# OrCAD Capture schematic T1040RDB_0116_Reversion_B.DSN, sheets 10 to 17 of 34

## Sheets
10 10 QE: size B
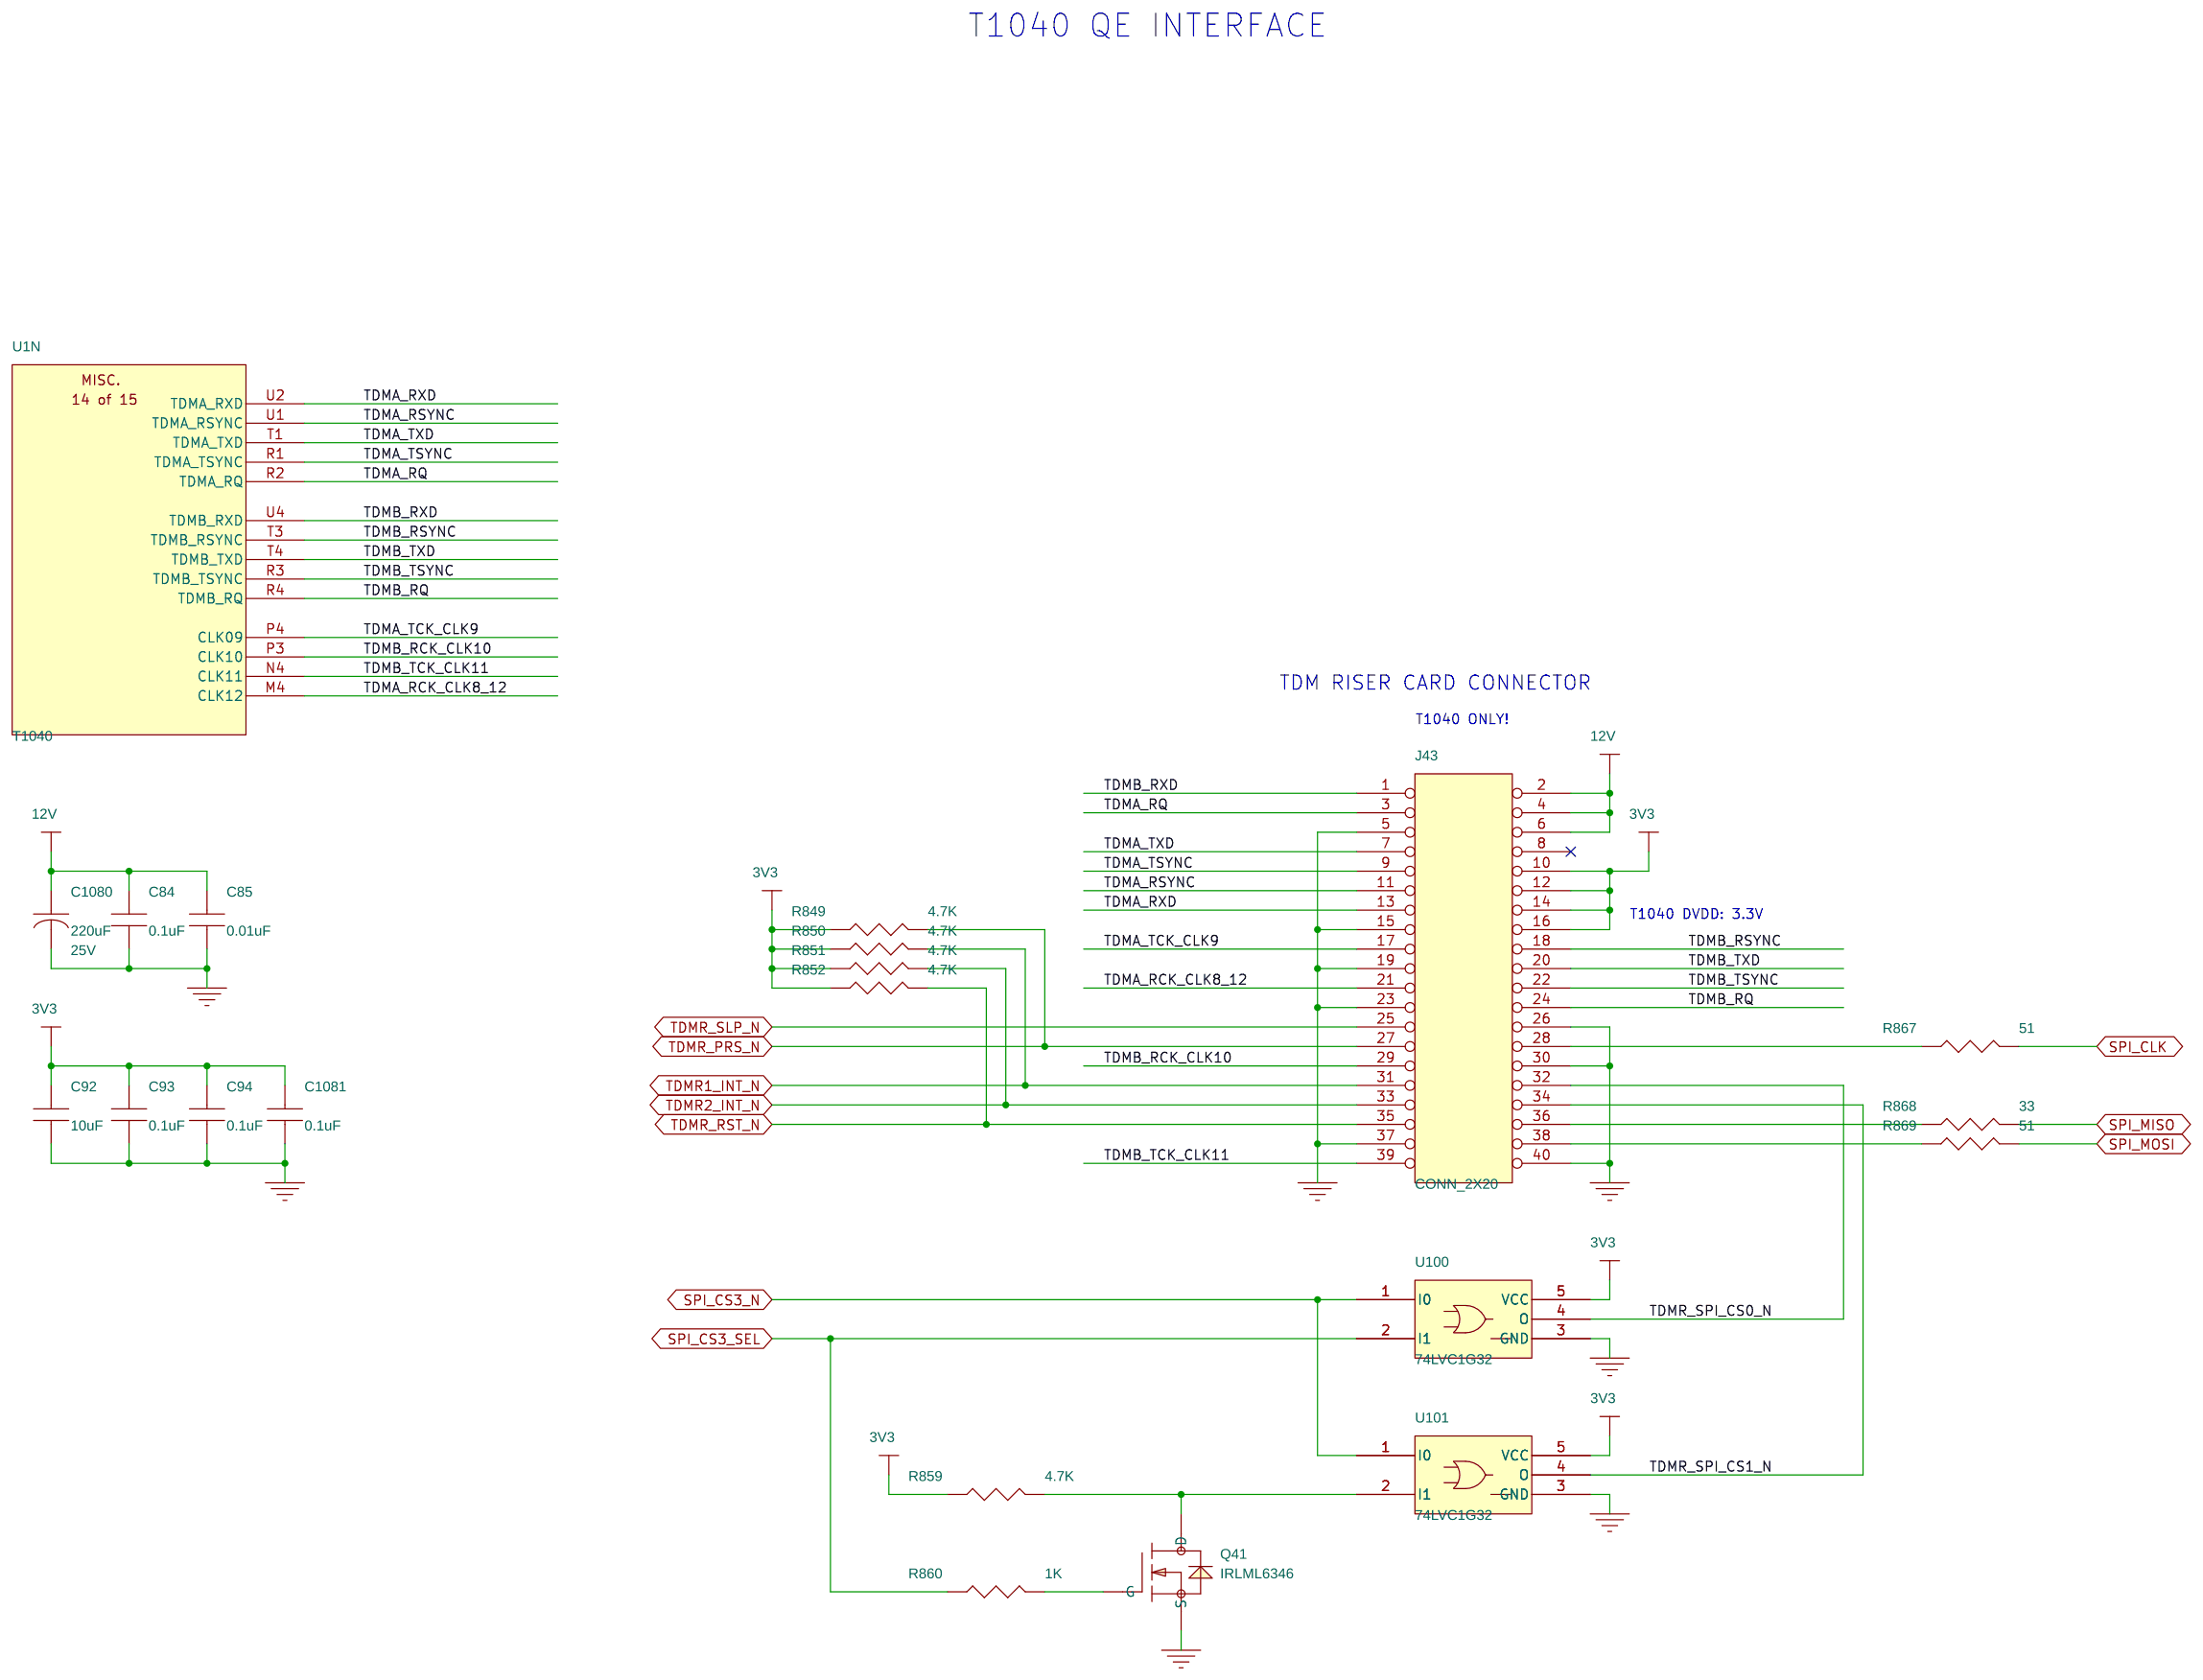
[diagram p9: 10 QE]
11 11 USB: size B
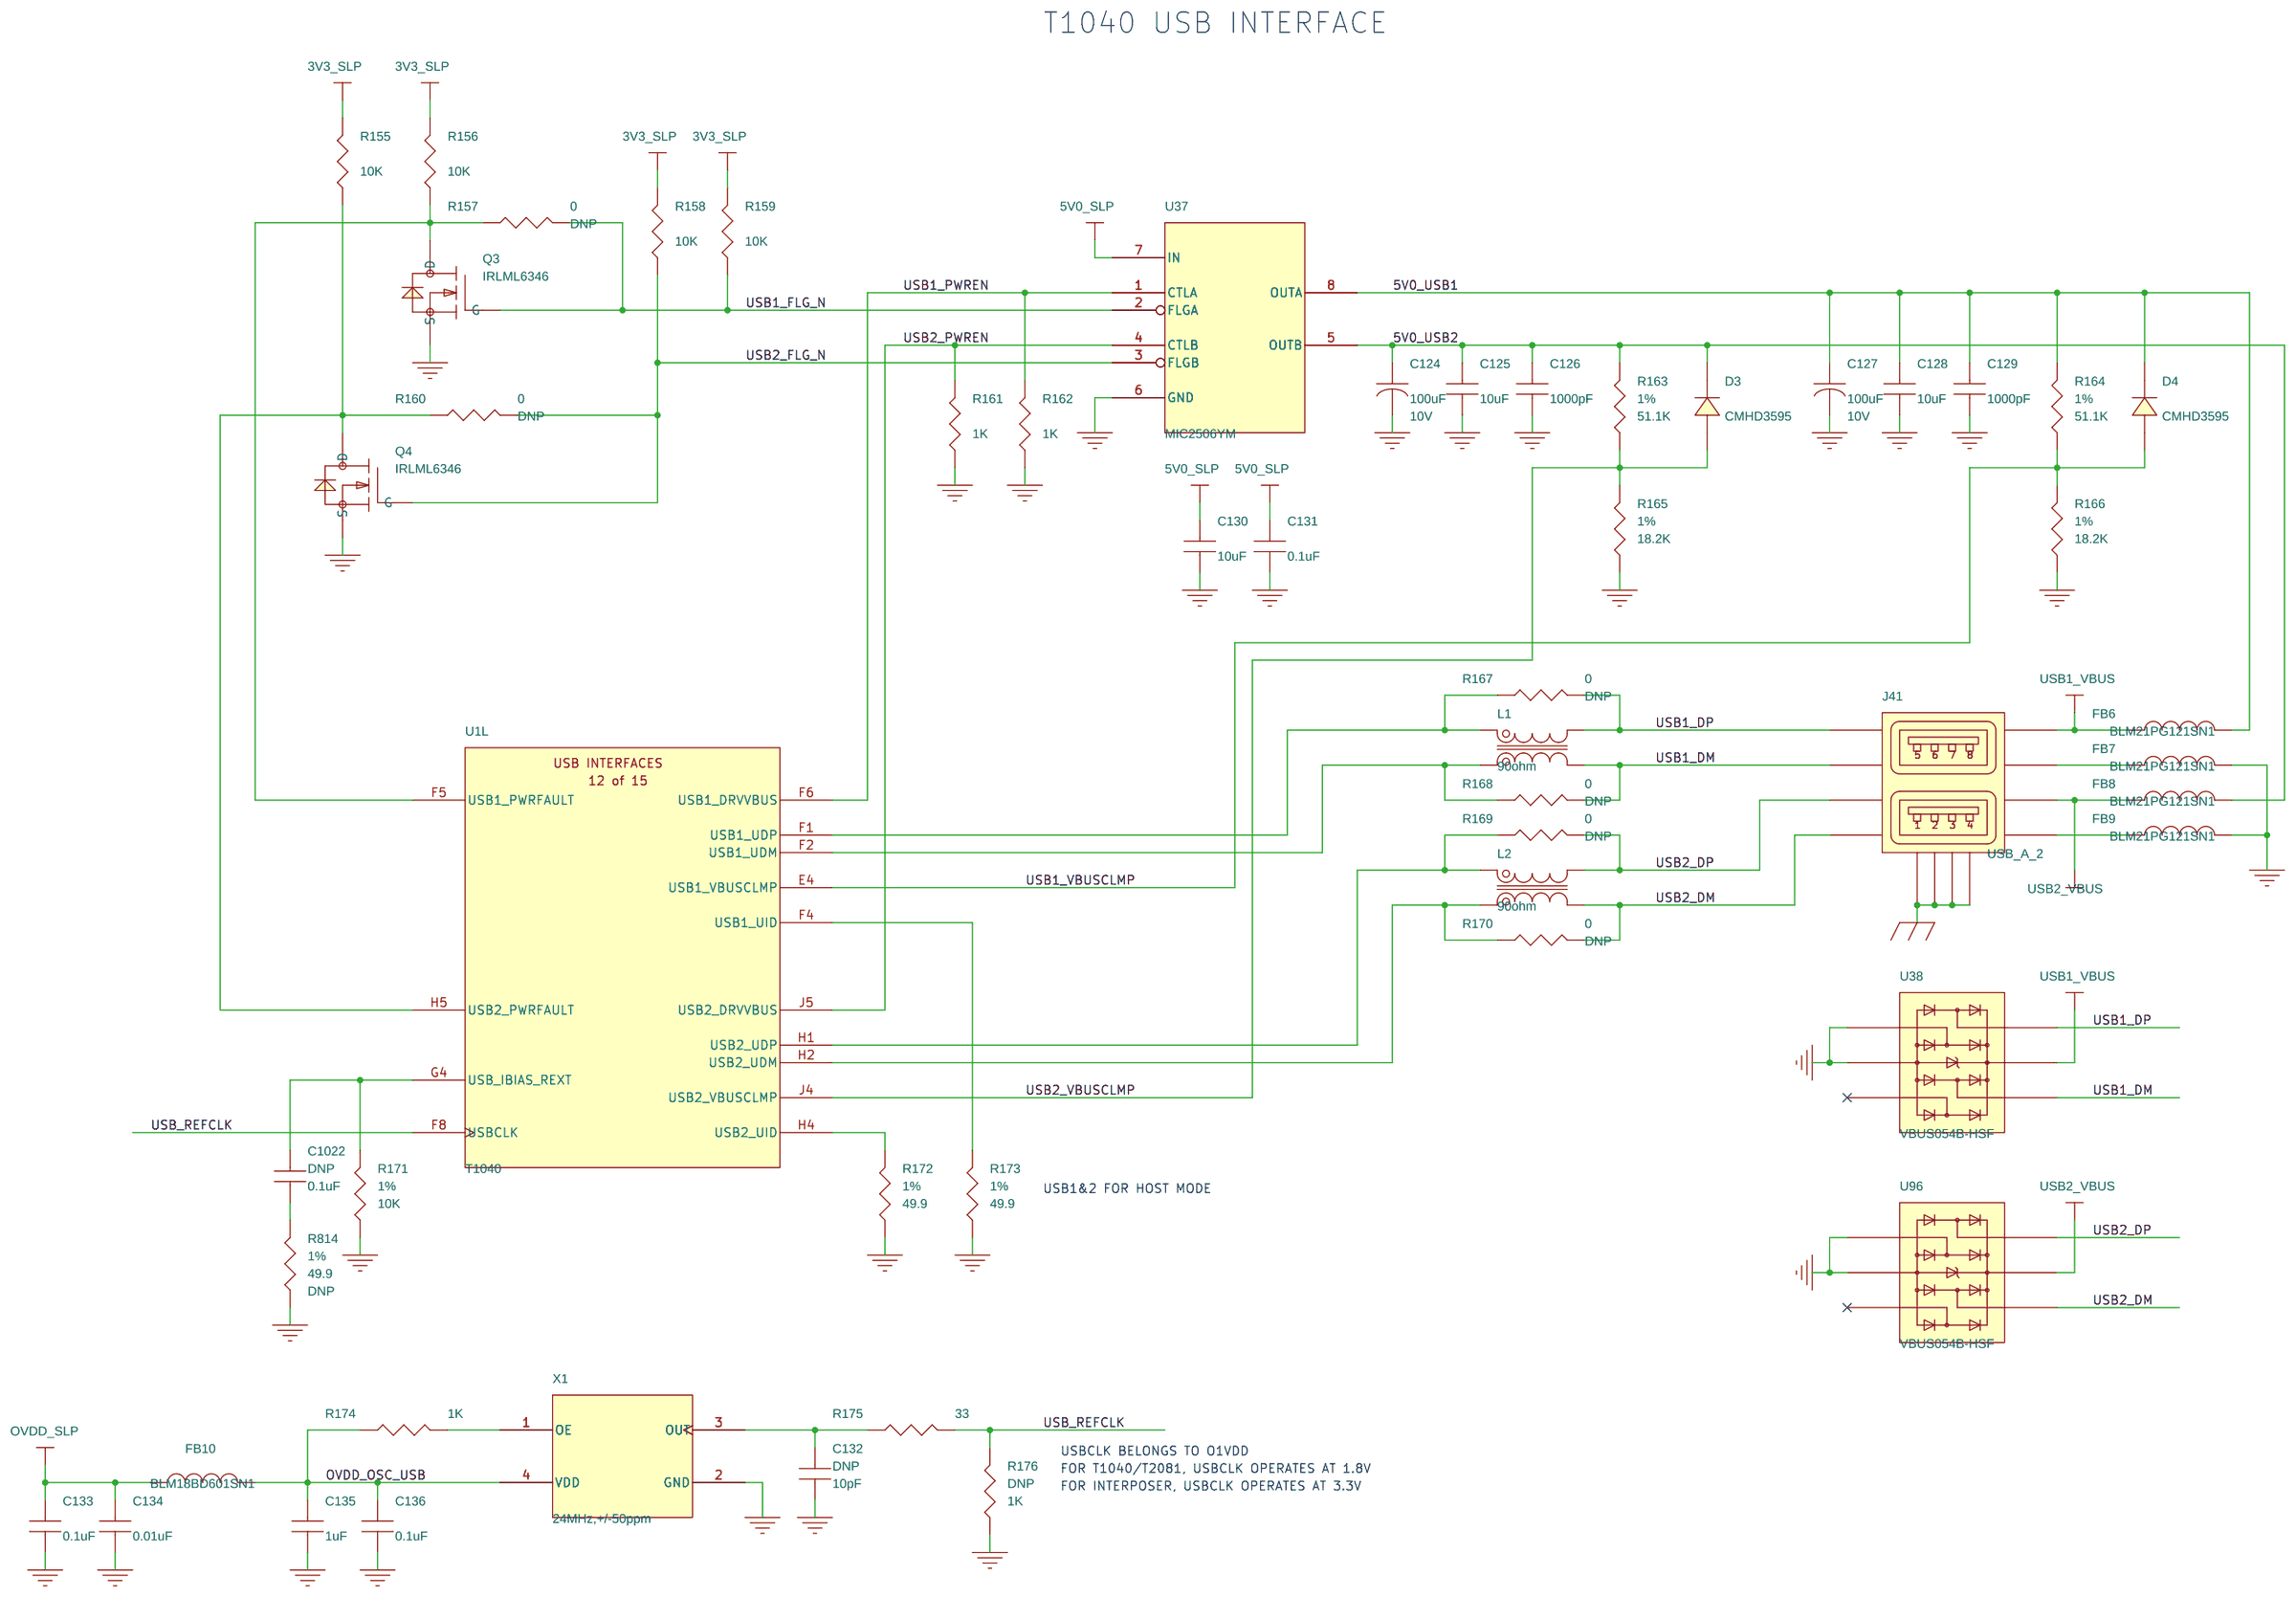
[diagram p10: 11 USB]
12 12 Proc Pwr: size B
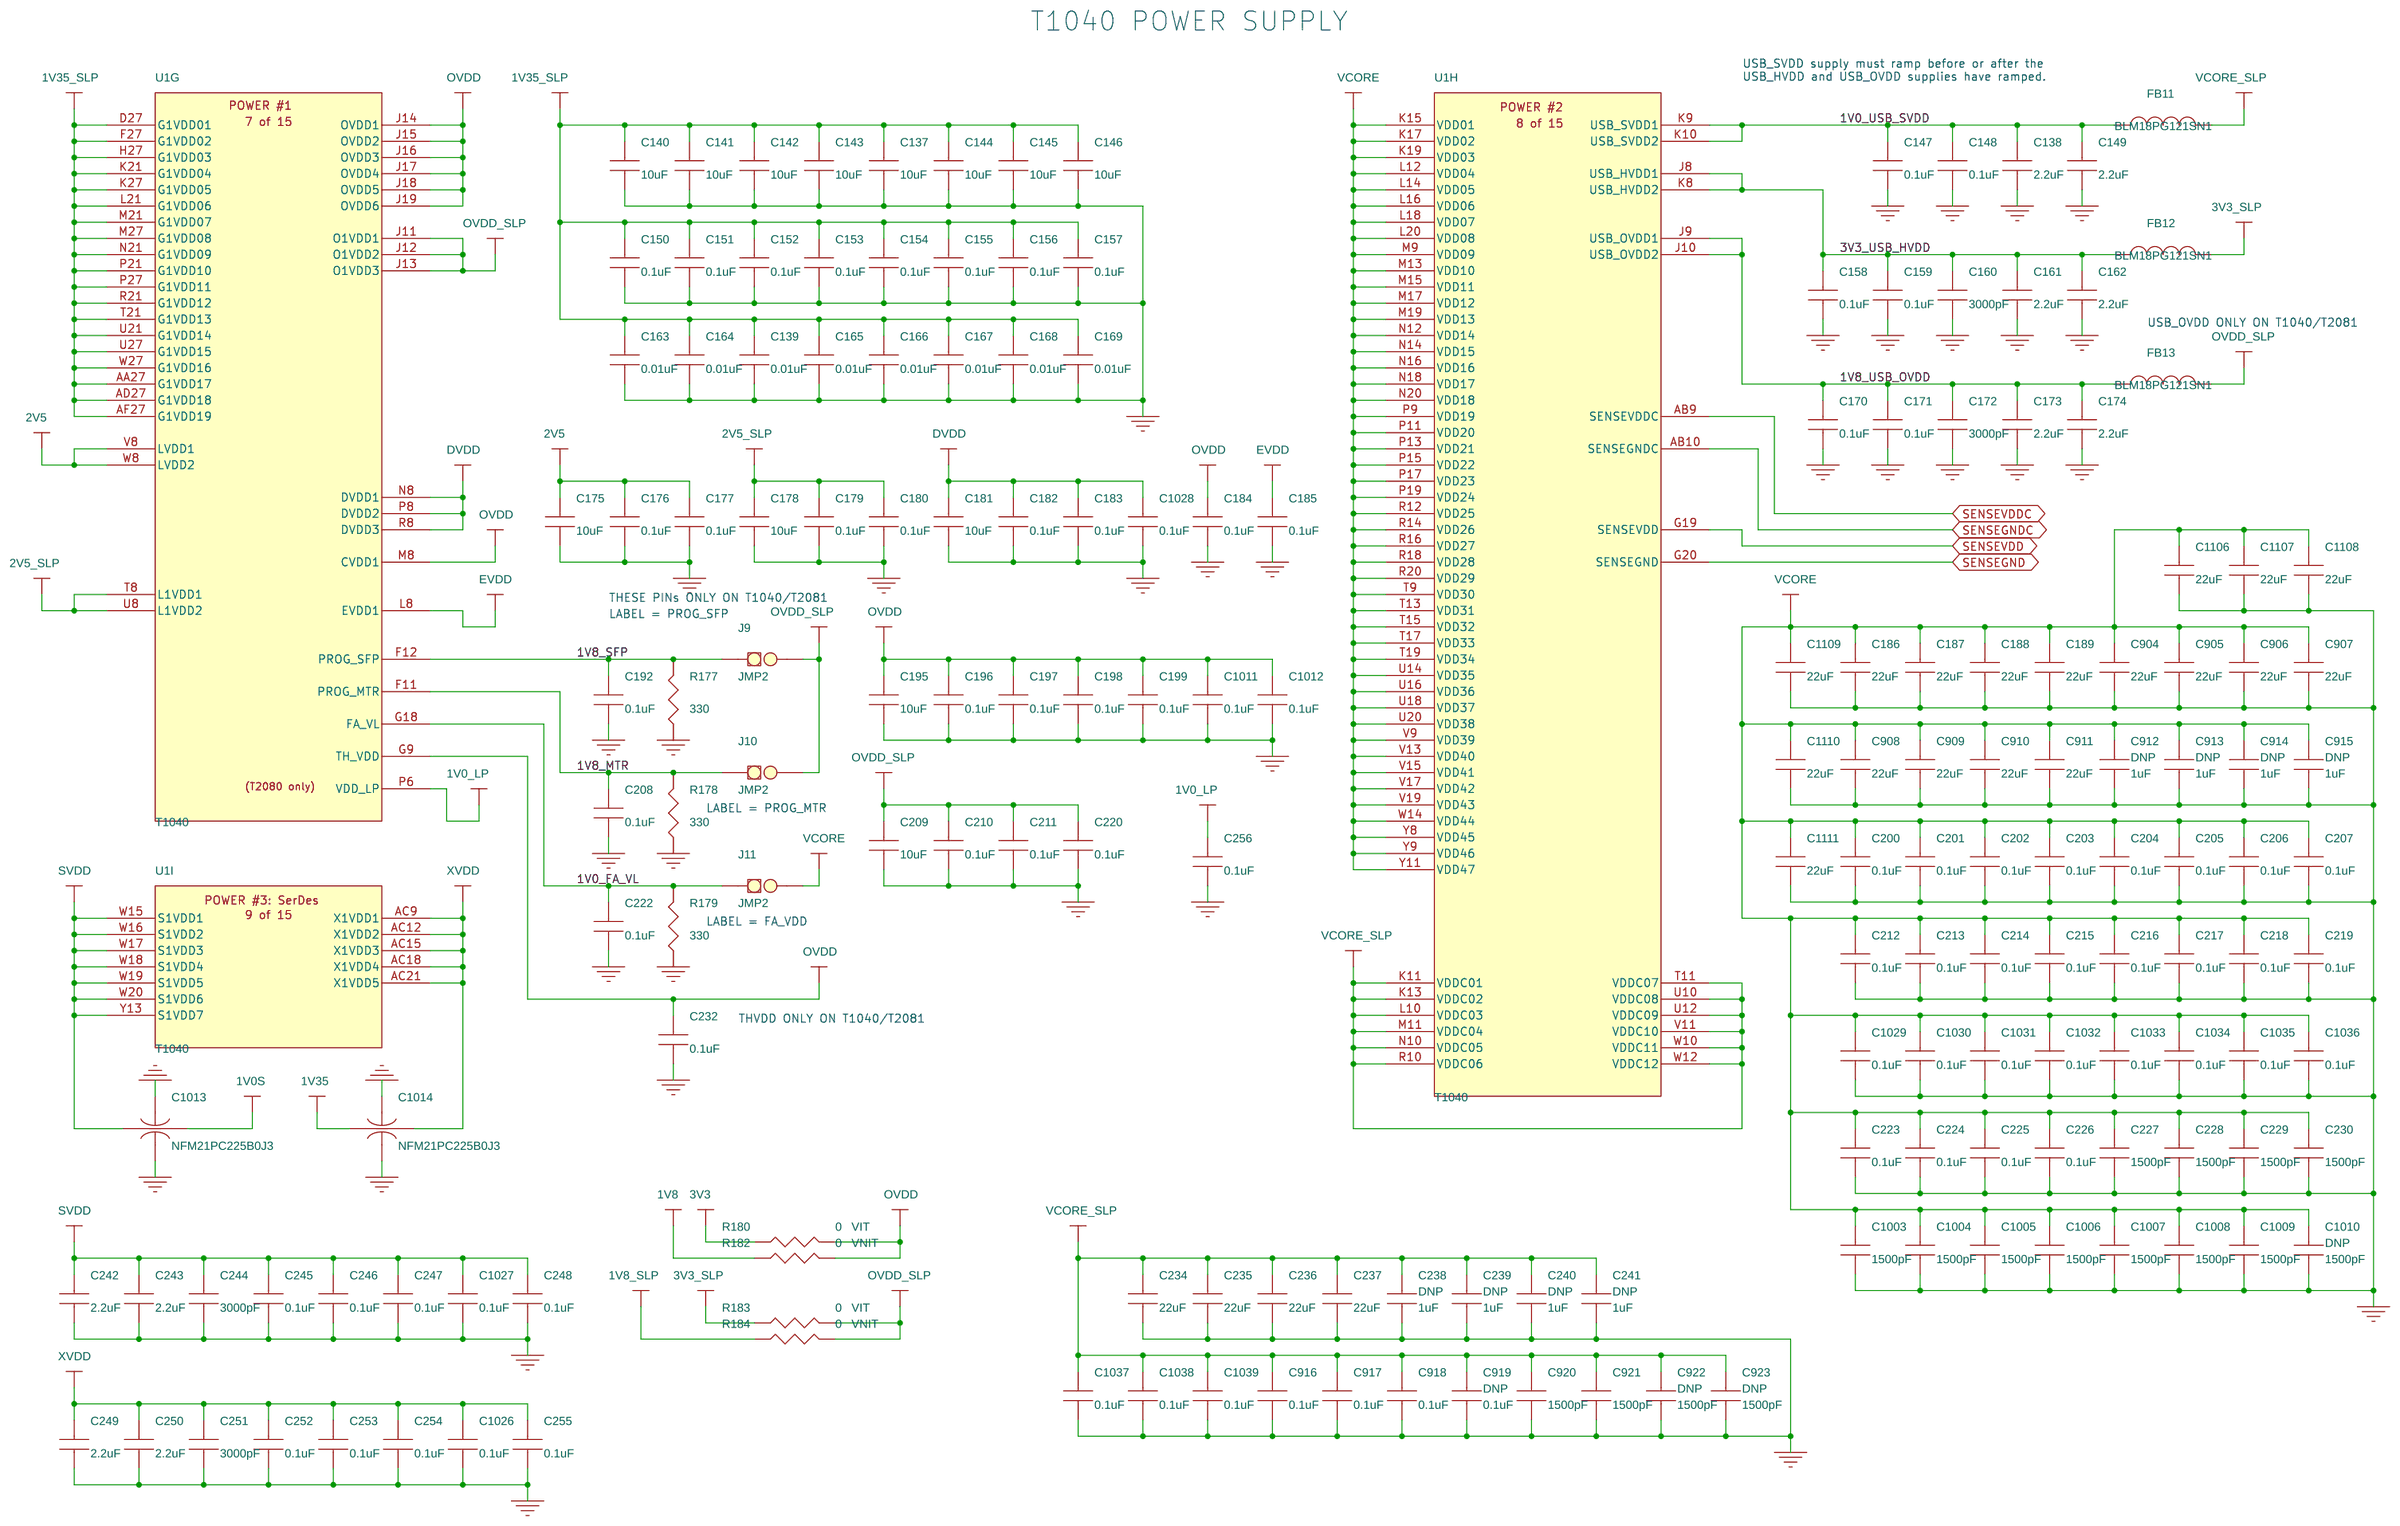
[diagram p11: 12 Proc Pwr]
13 13 Proc Gnd: size B
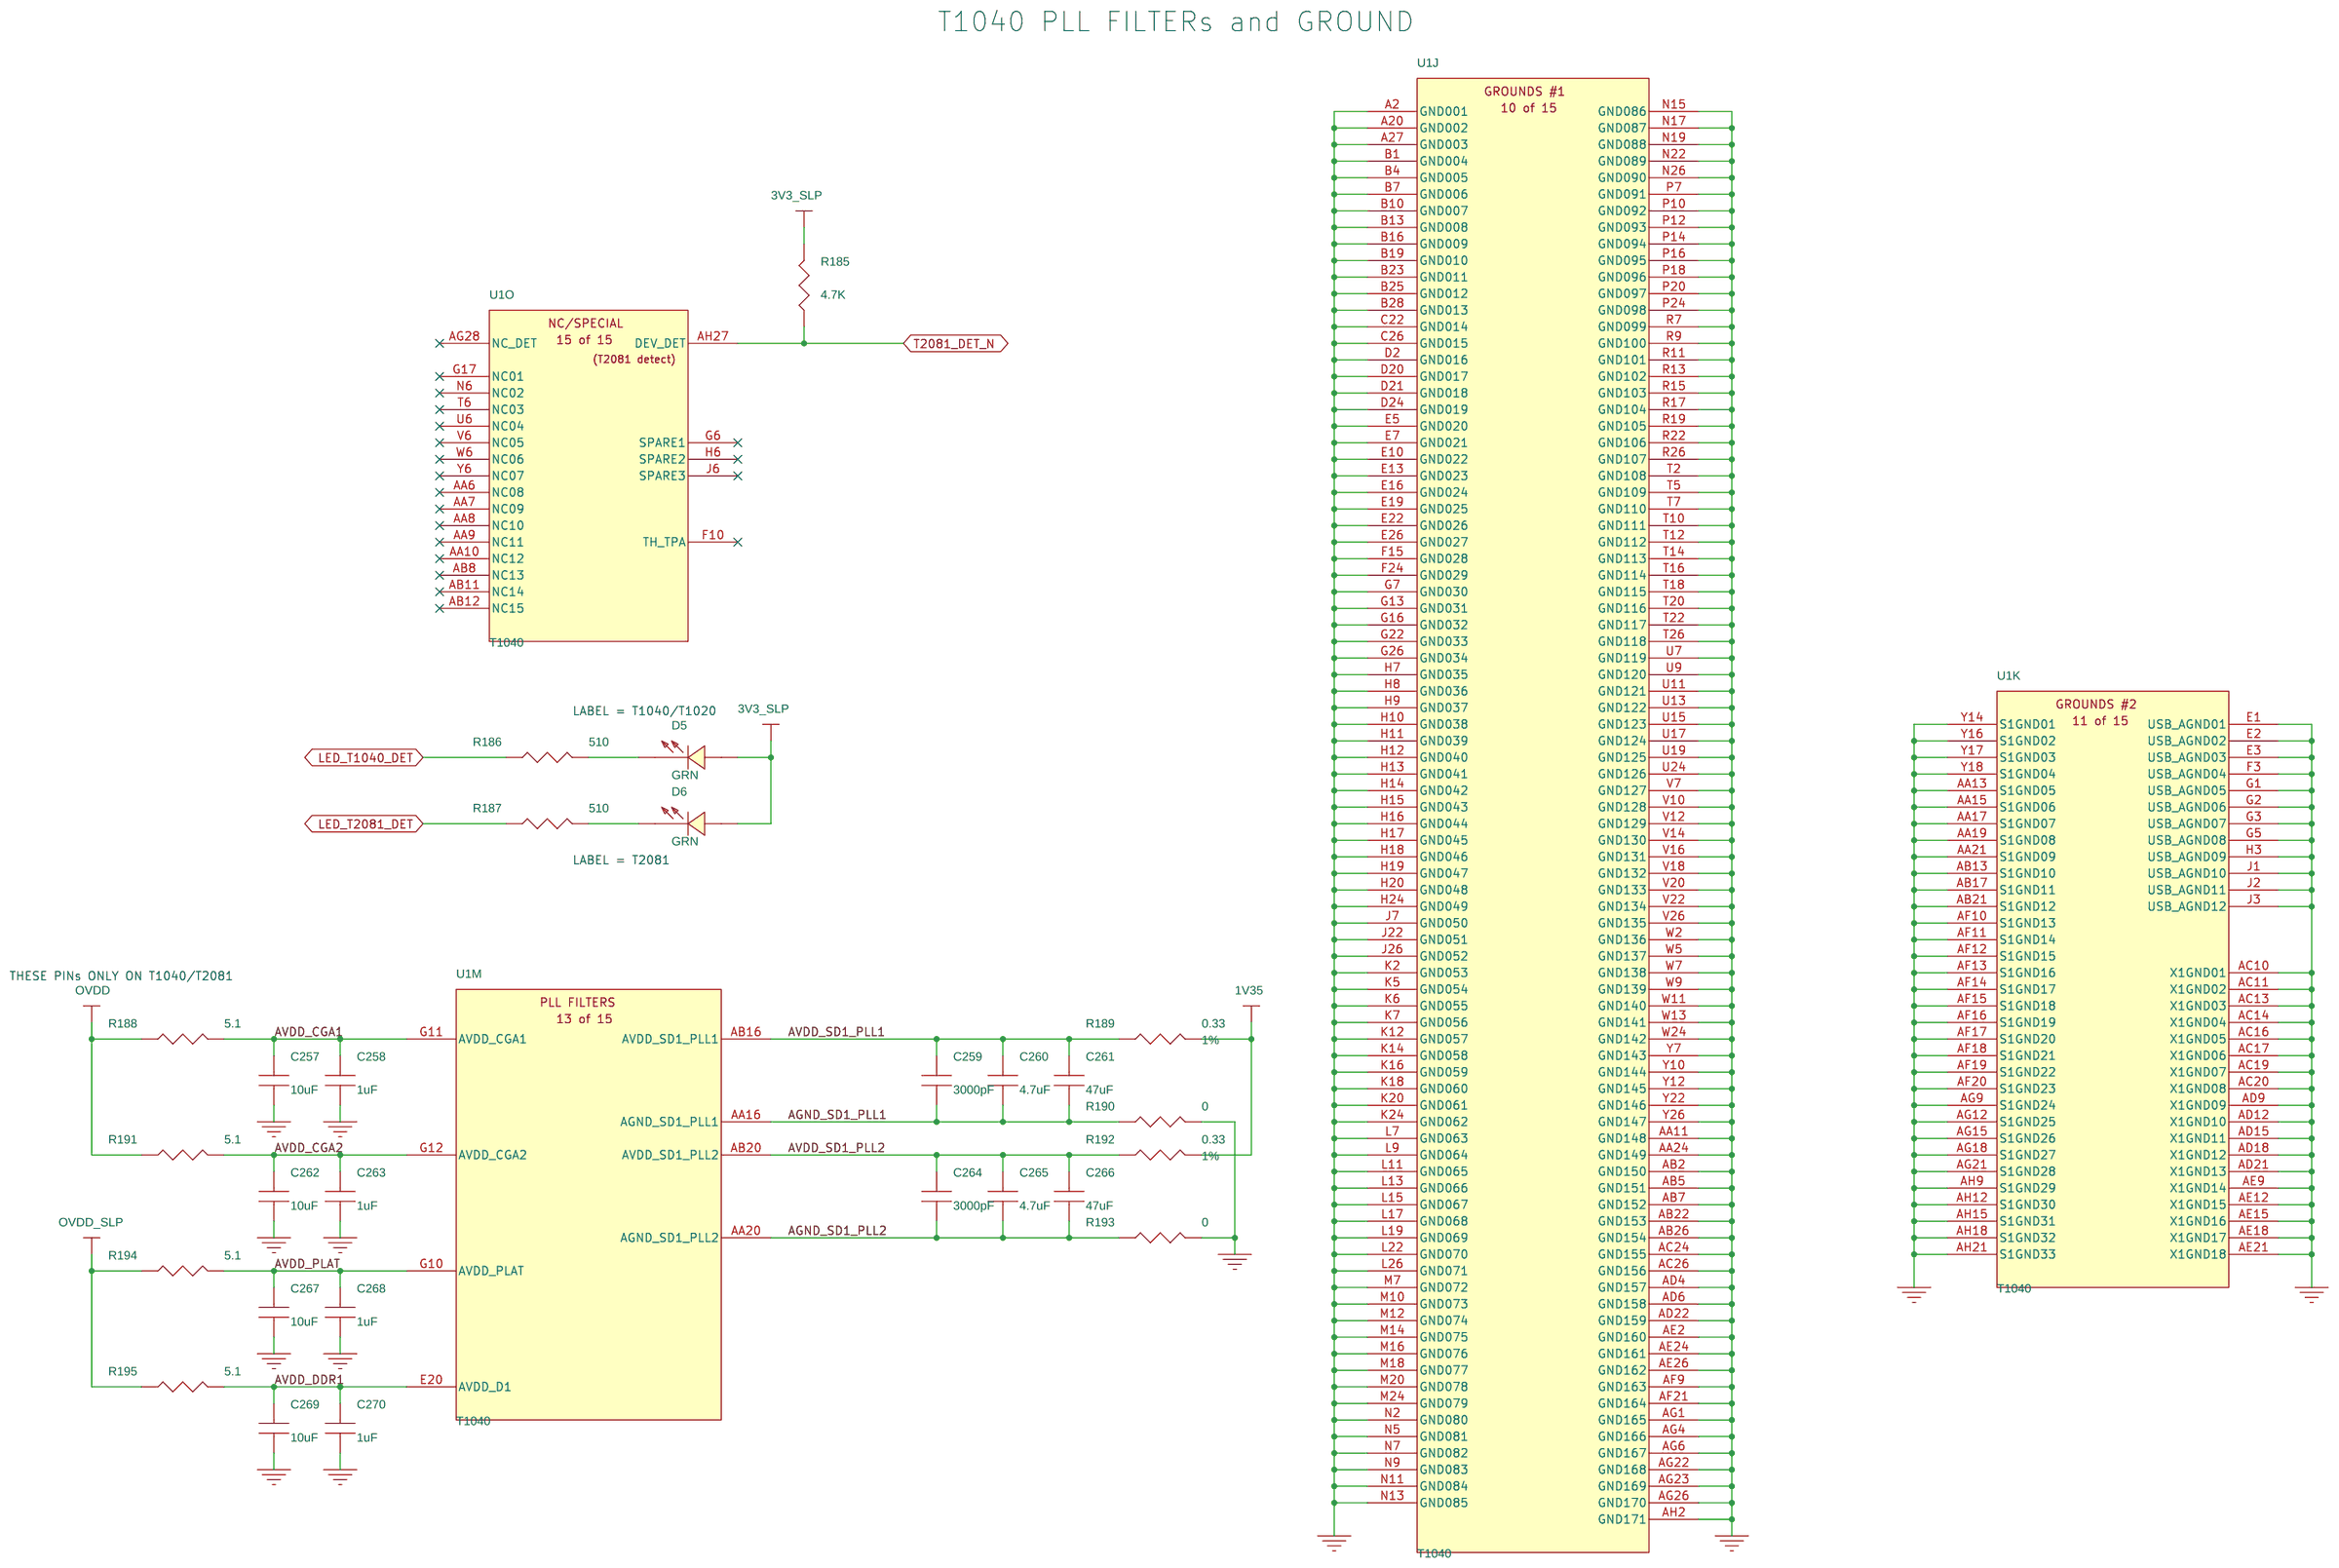
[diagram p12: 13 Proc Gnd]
14 14 UART&I2C: size B
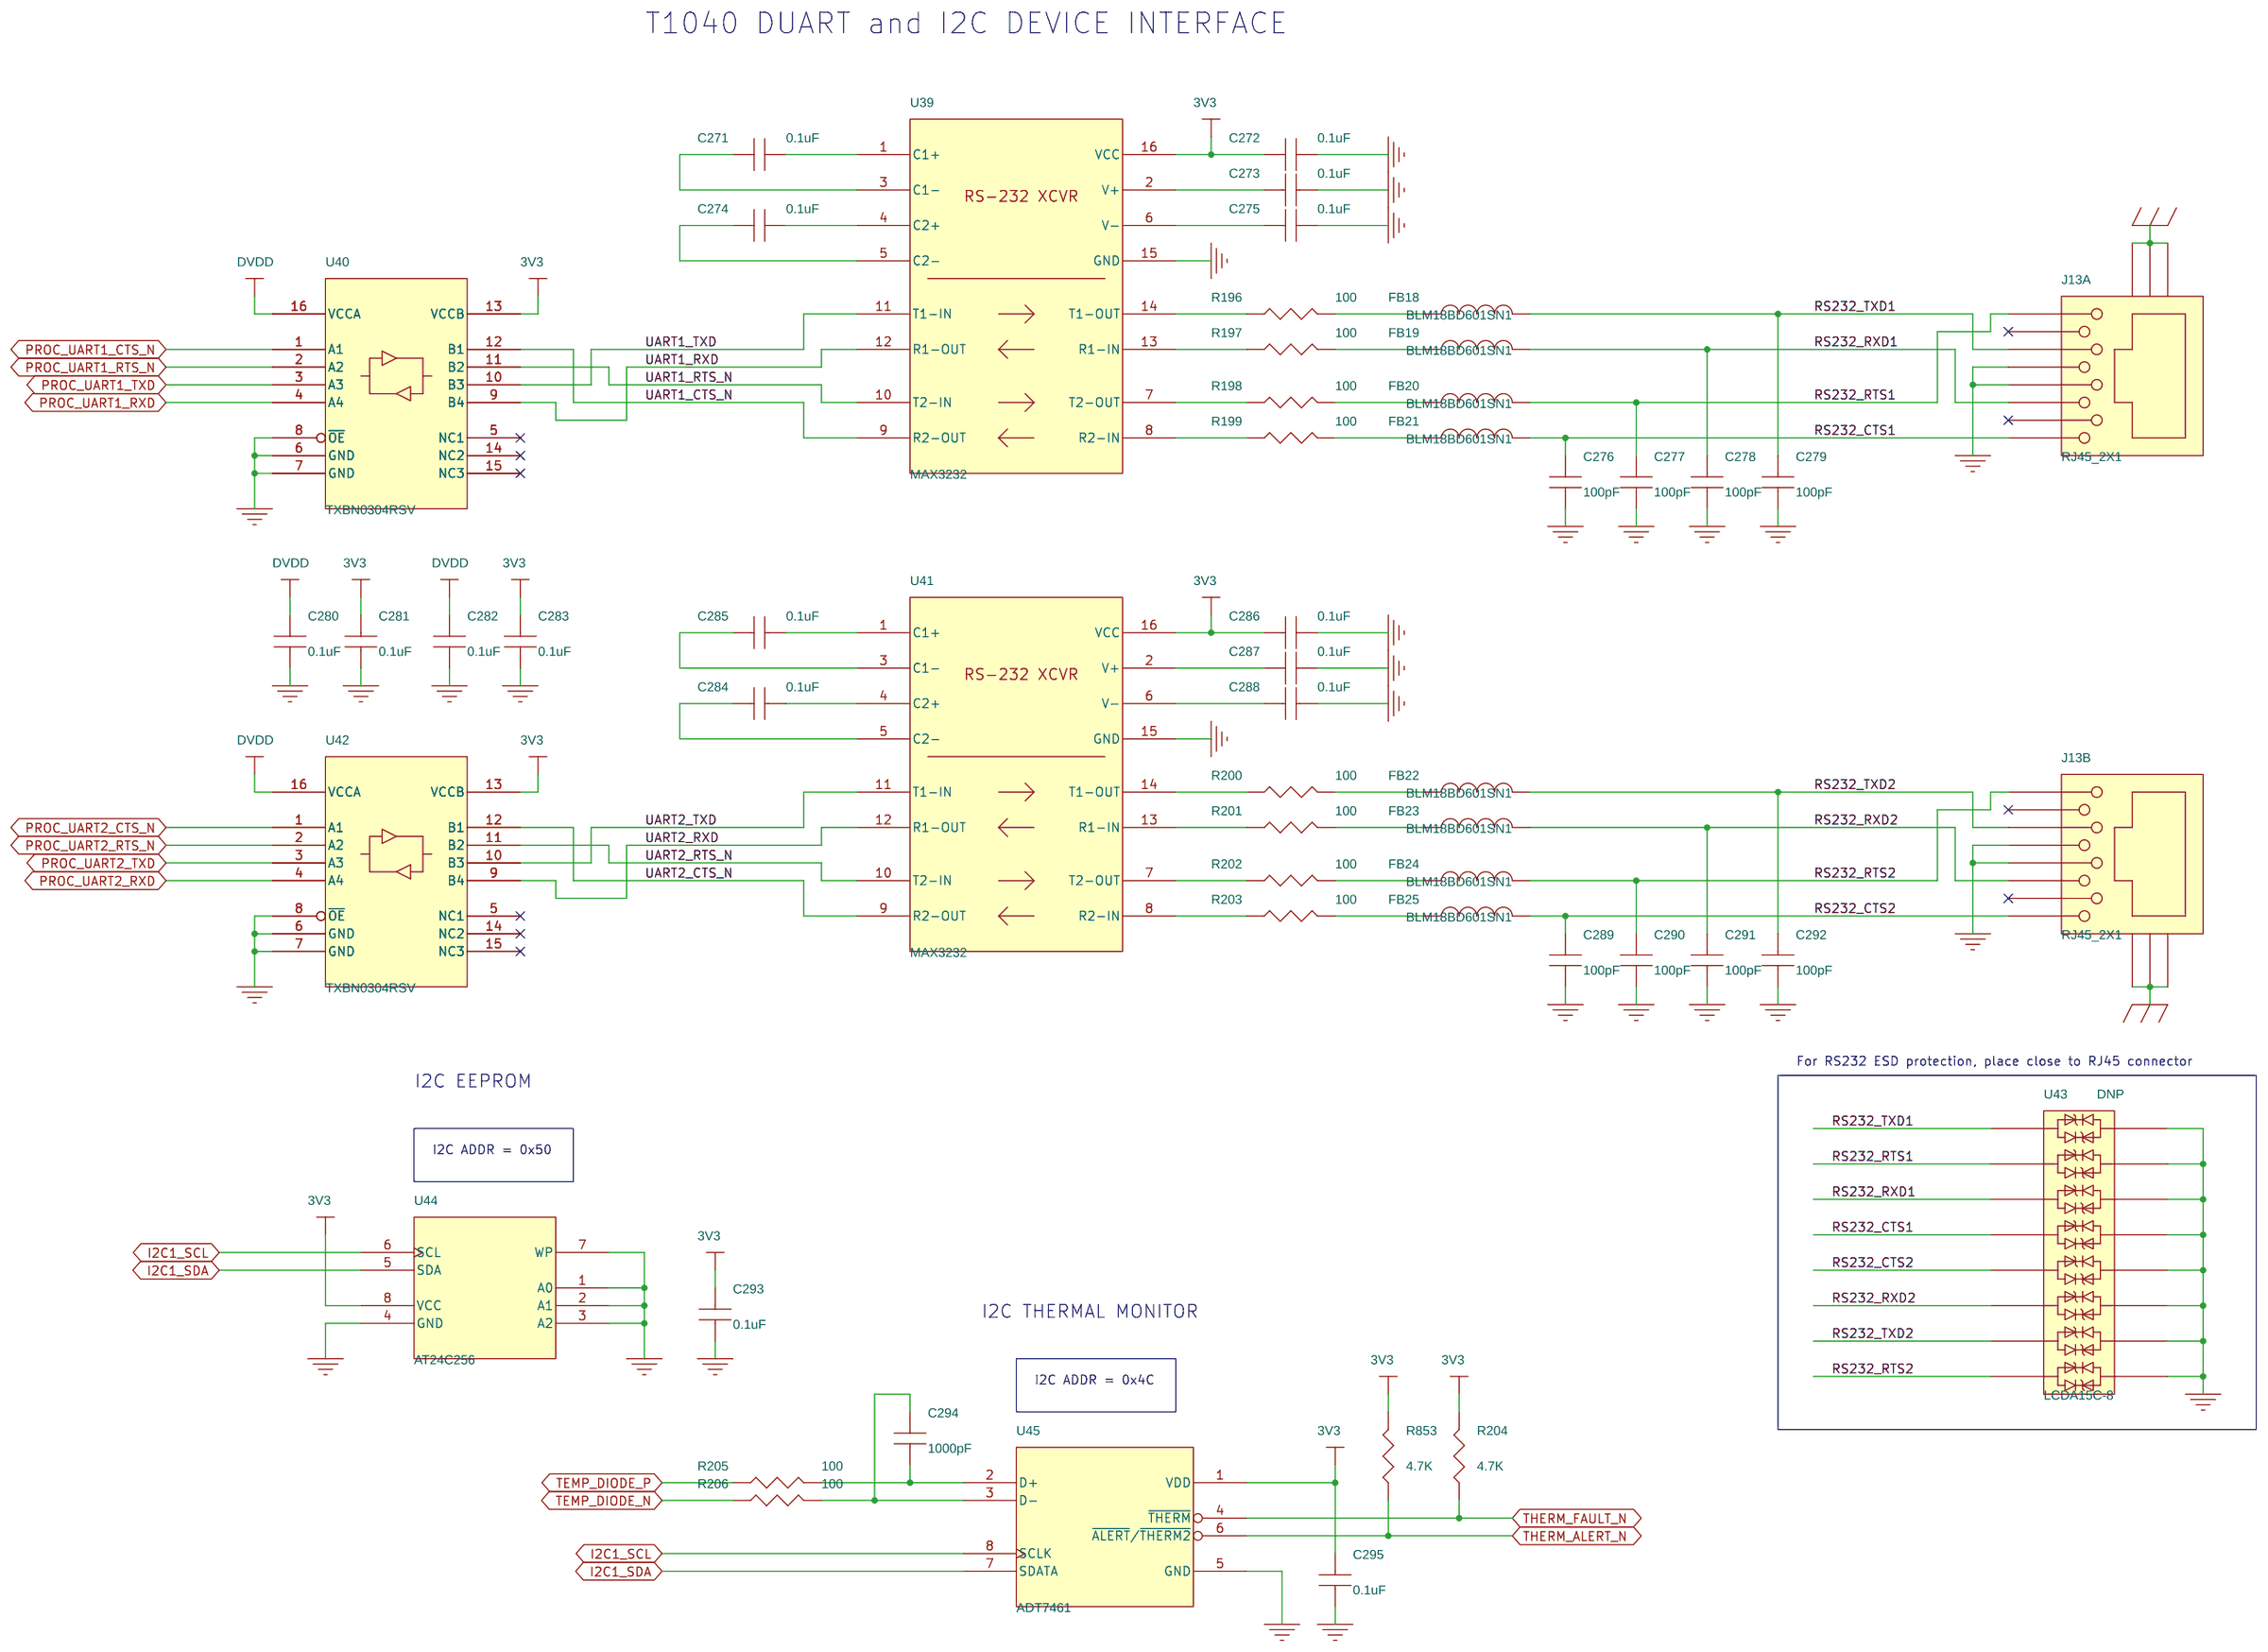
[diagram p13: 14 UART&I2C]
15 15 EC1 PHY: size B
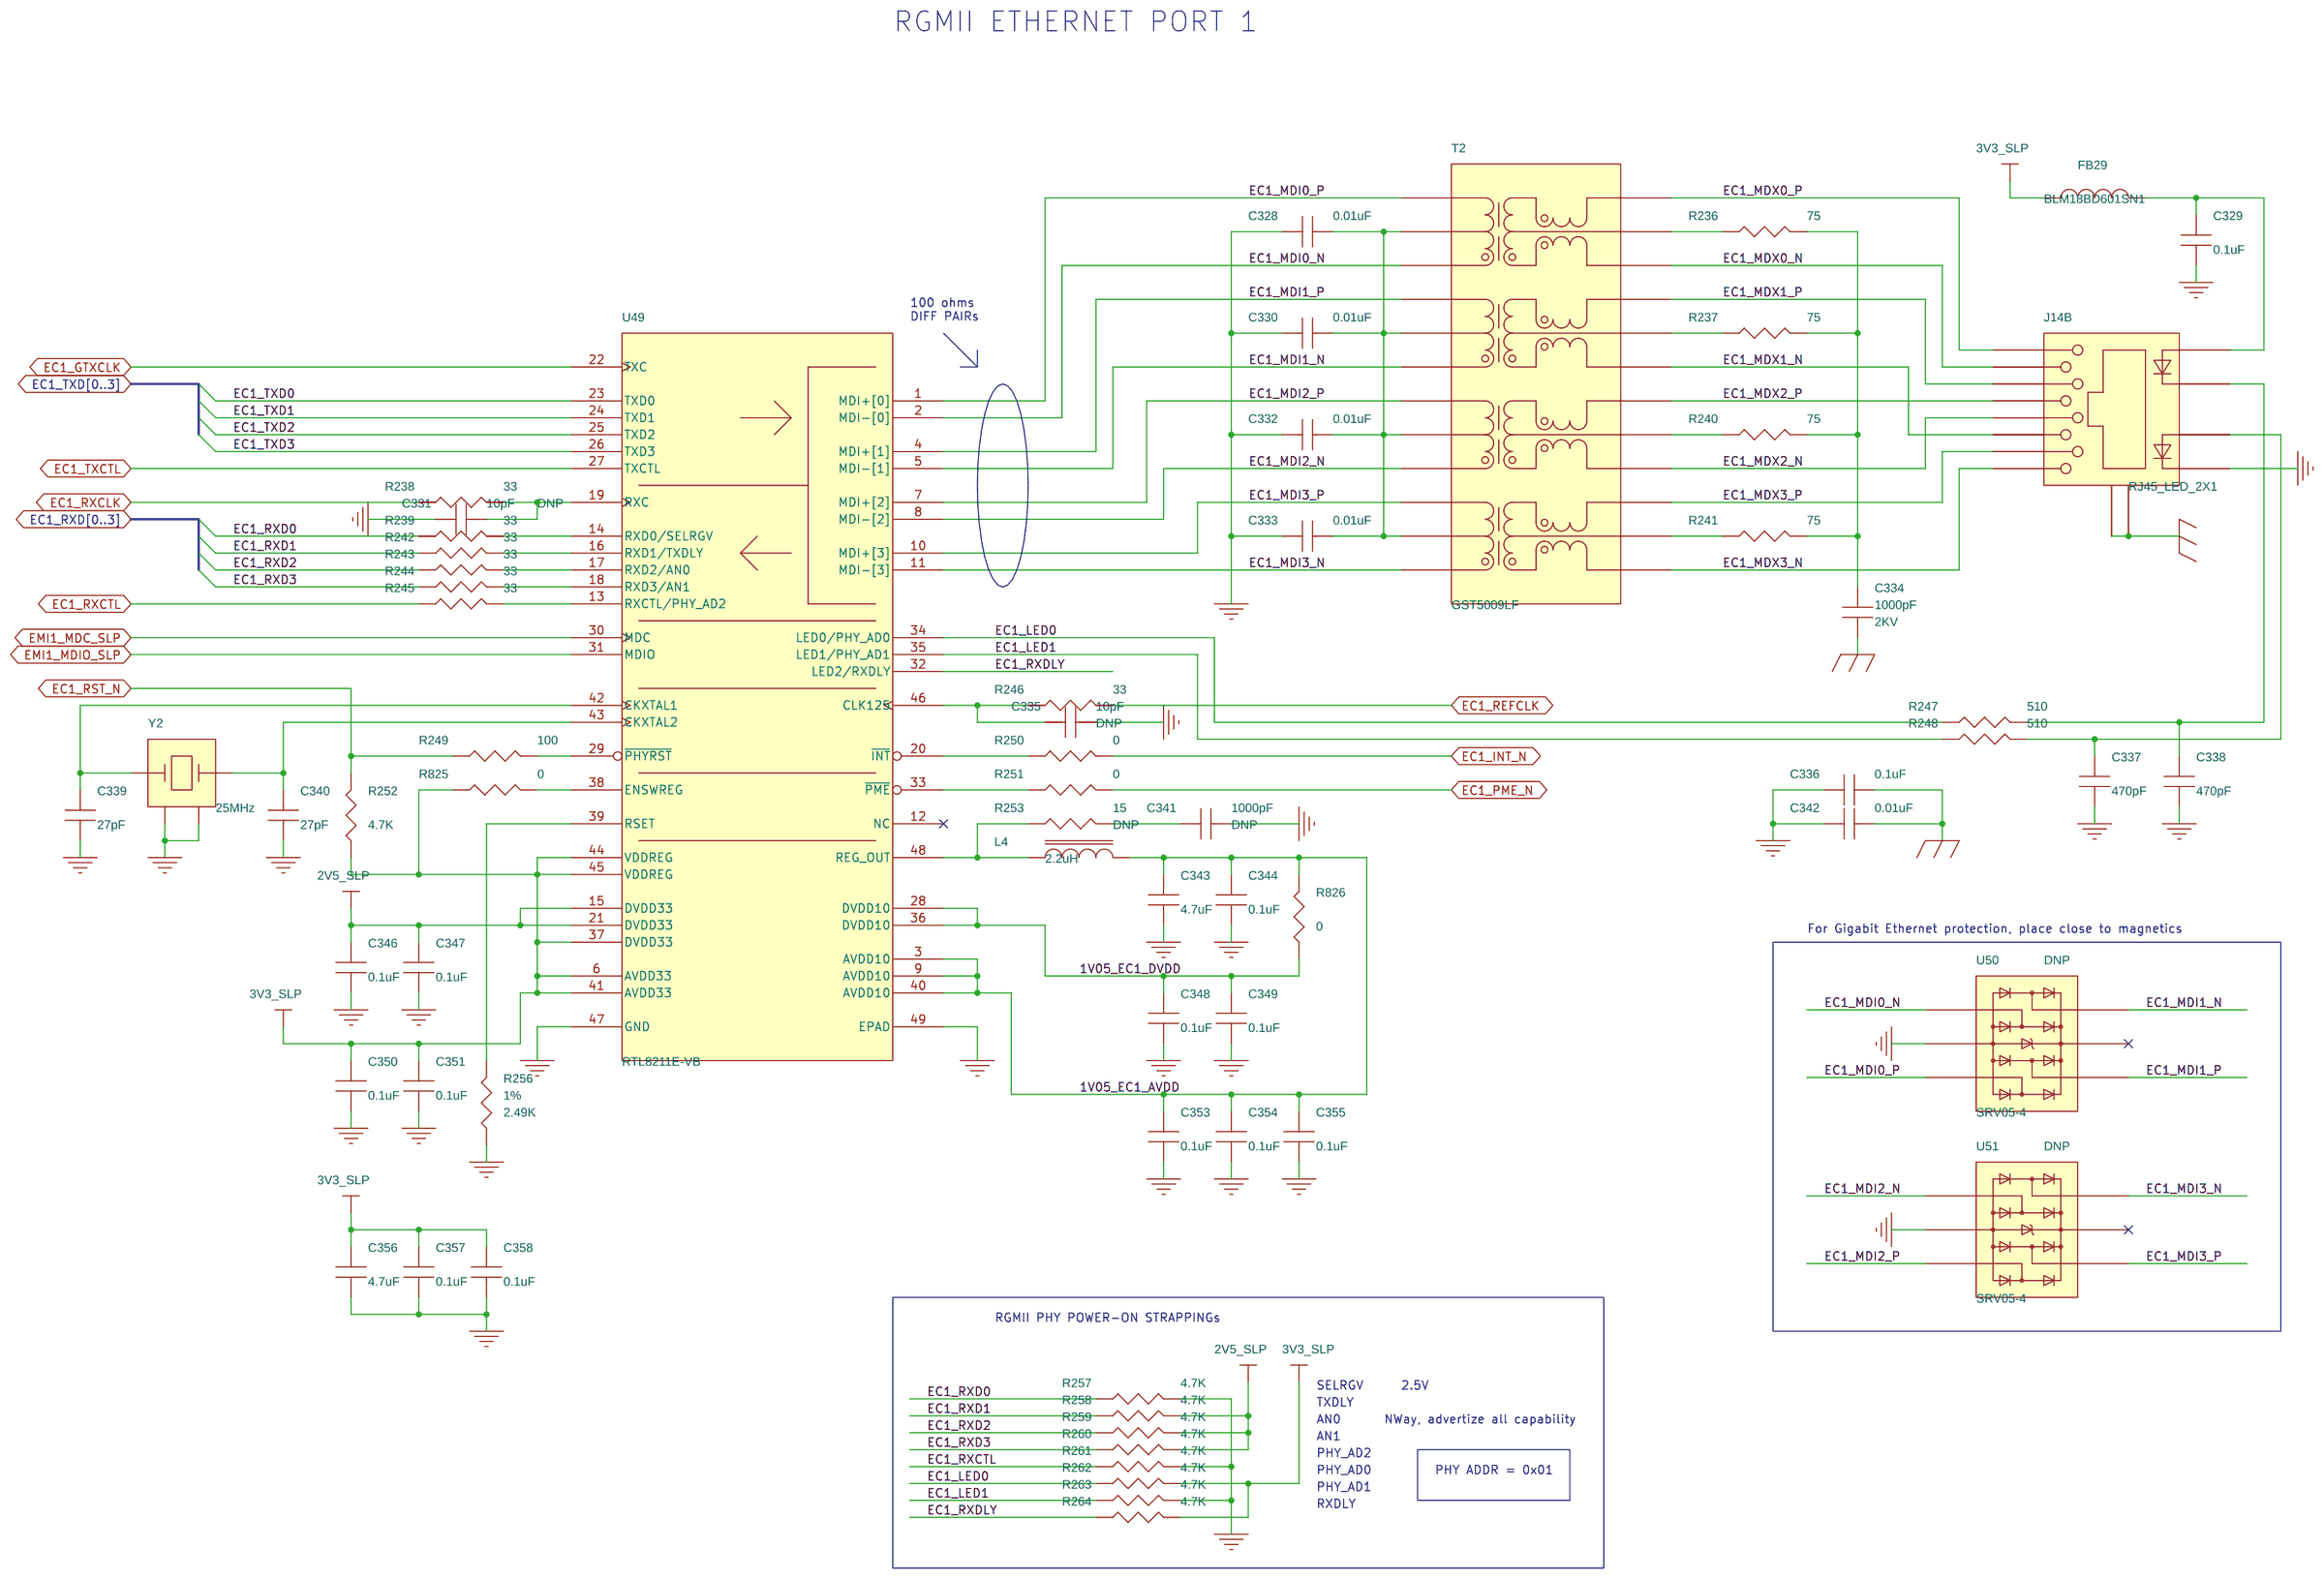
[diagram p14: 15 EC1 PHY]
16 16 EC2 PHY: size B
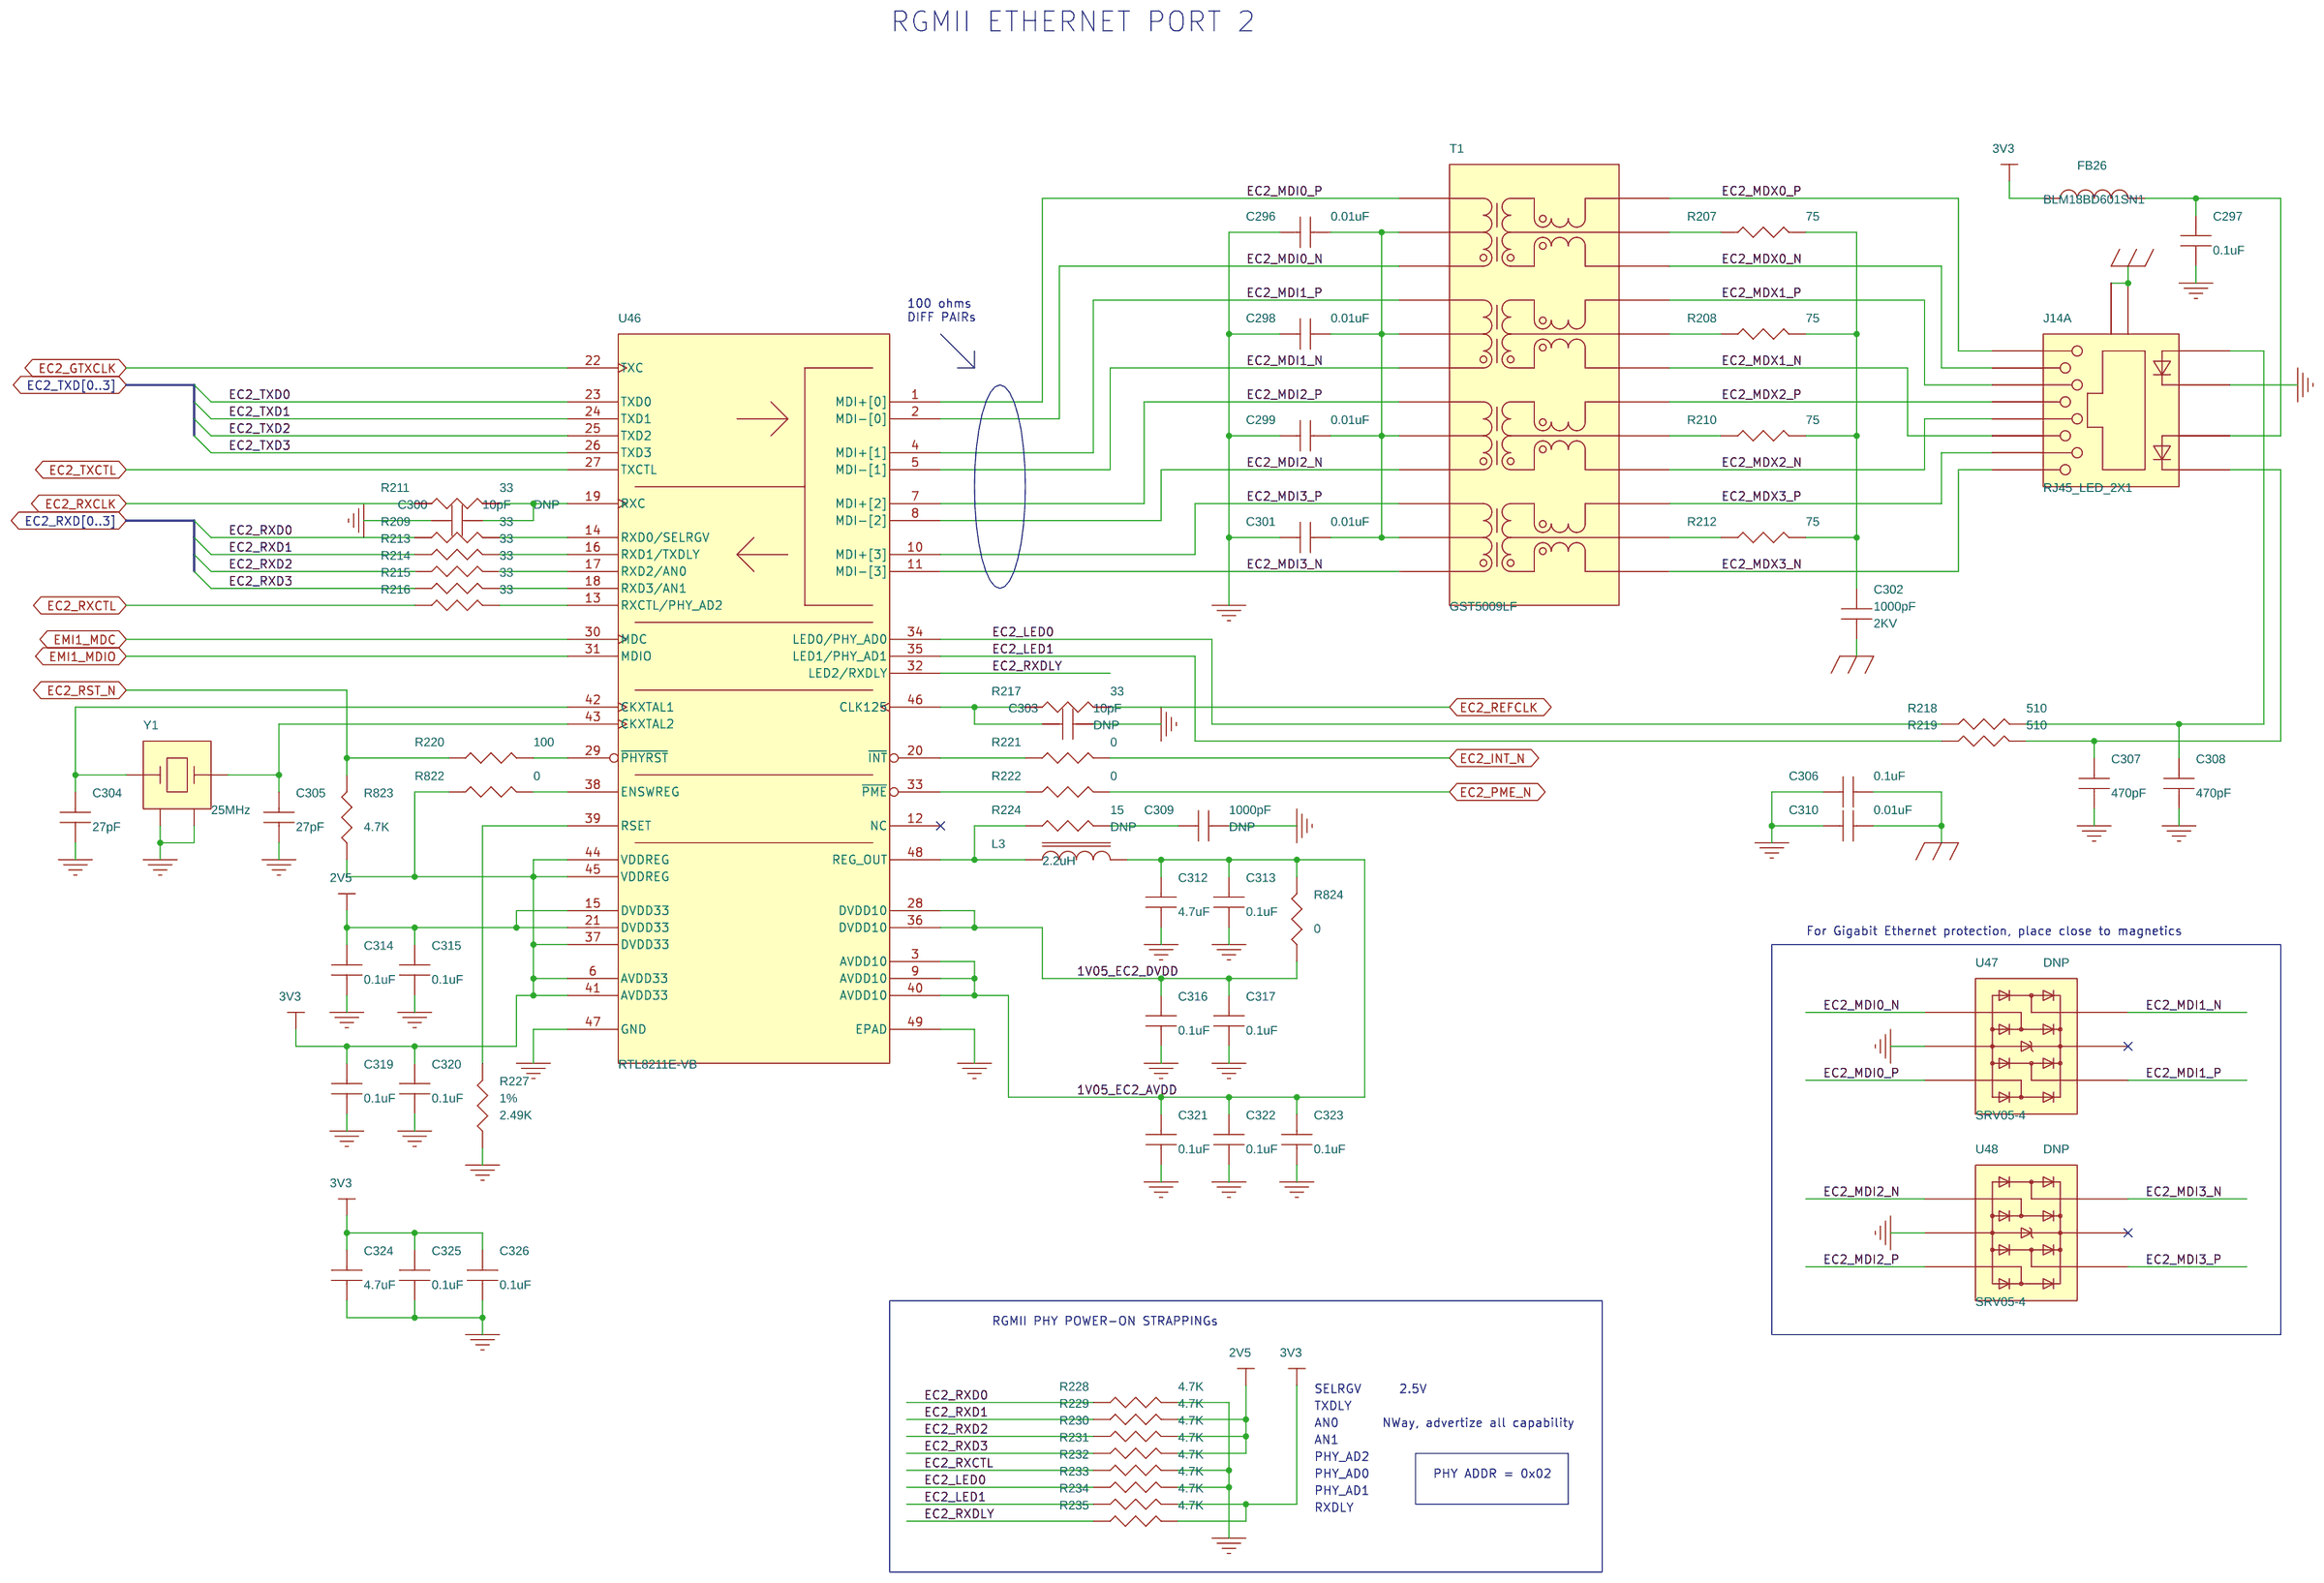
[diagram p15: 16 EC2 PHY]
17 17 SG PHY: size B
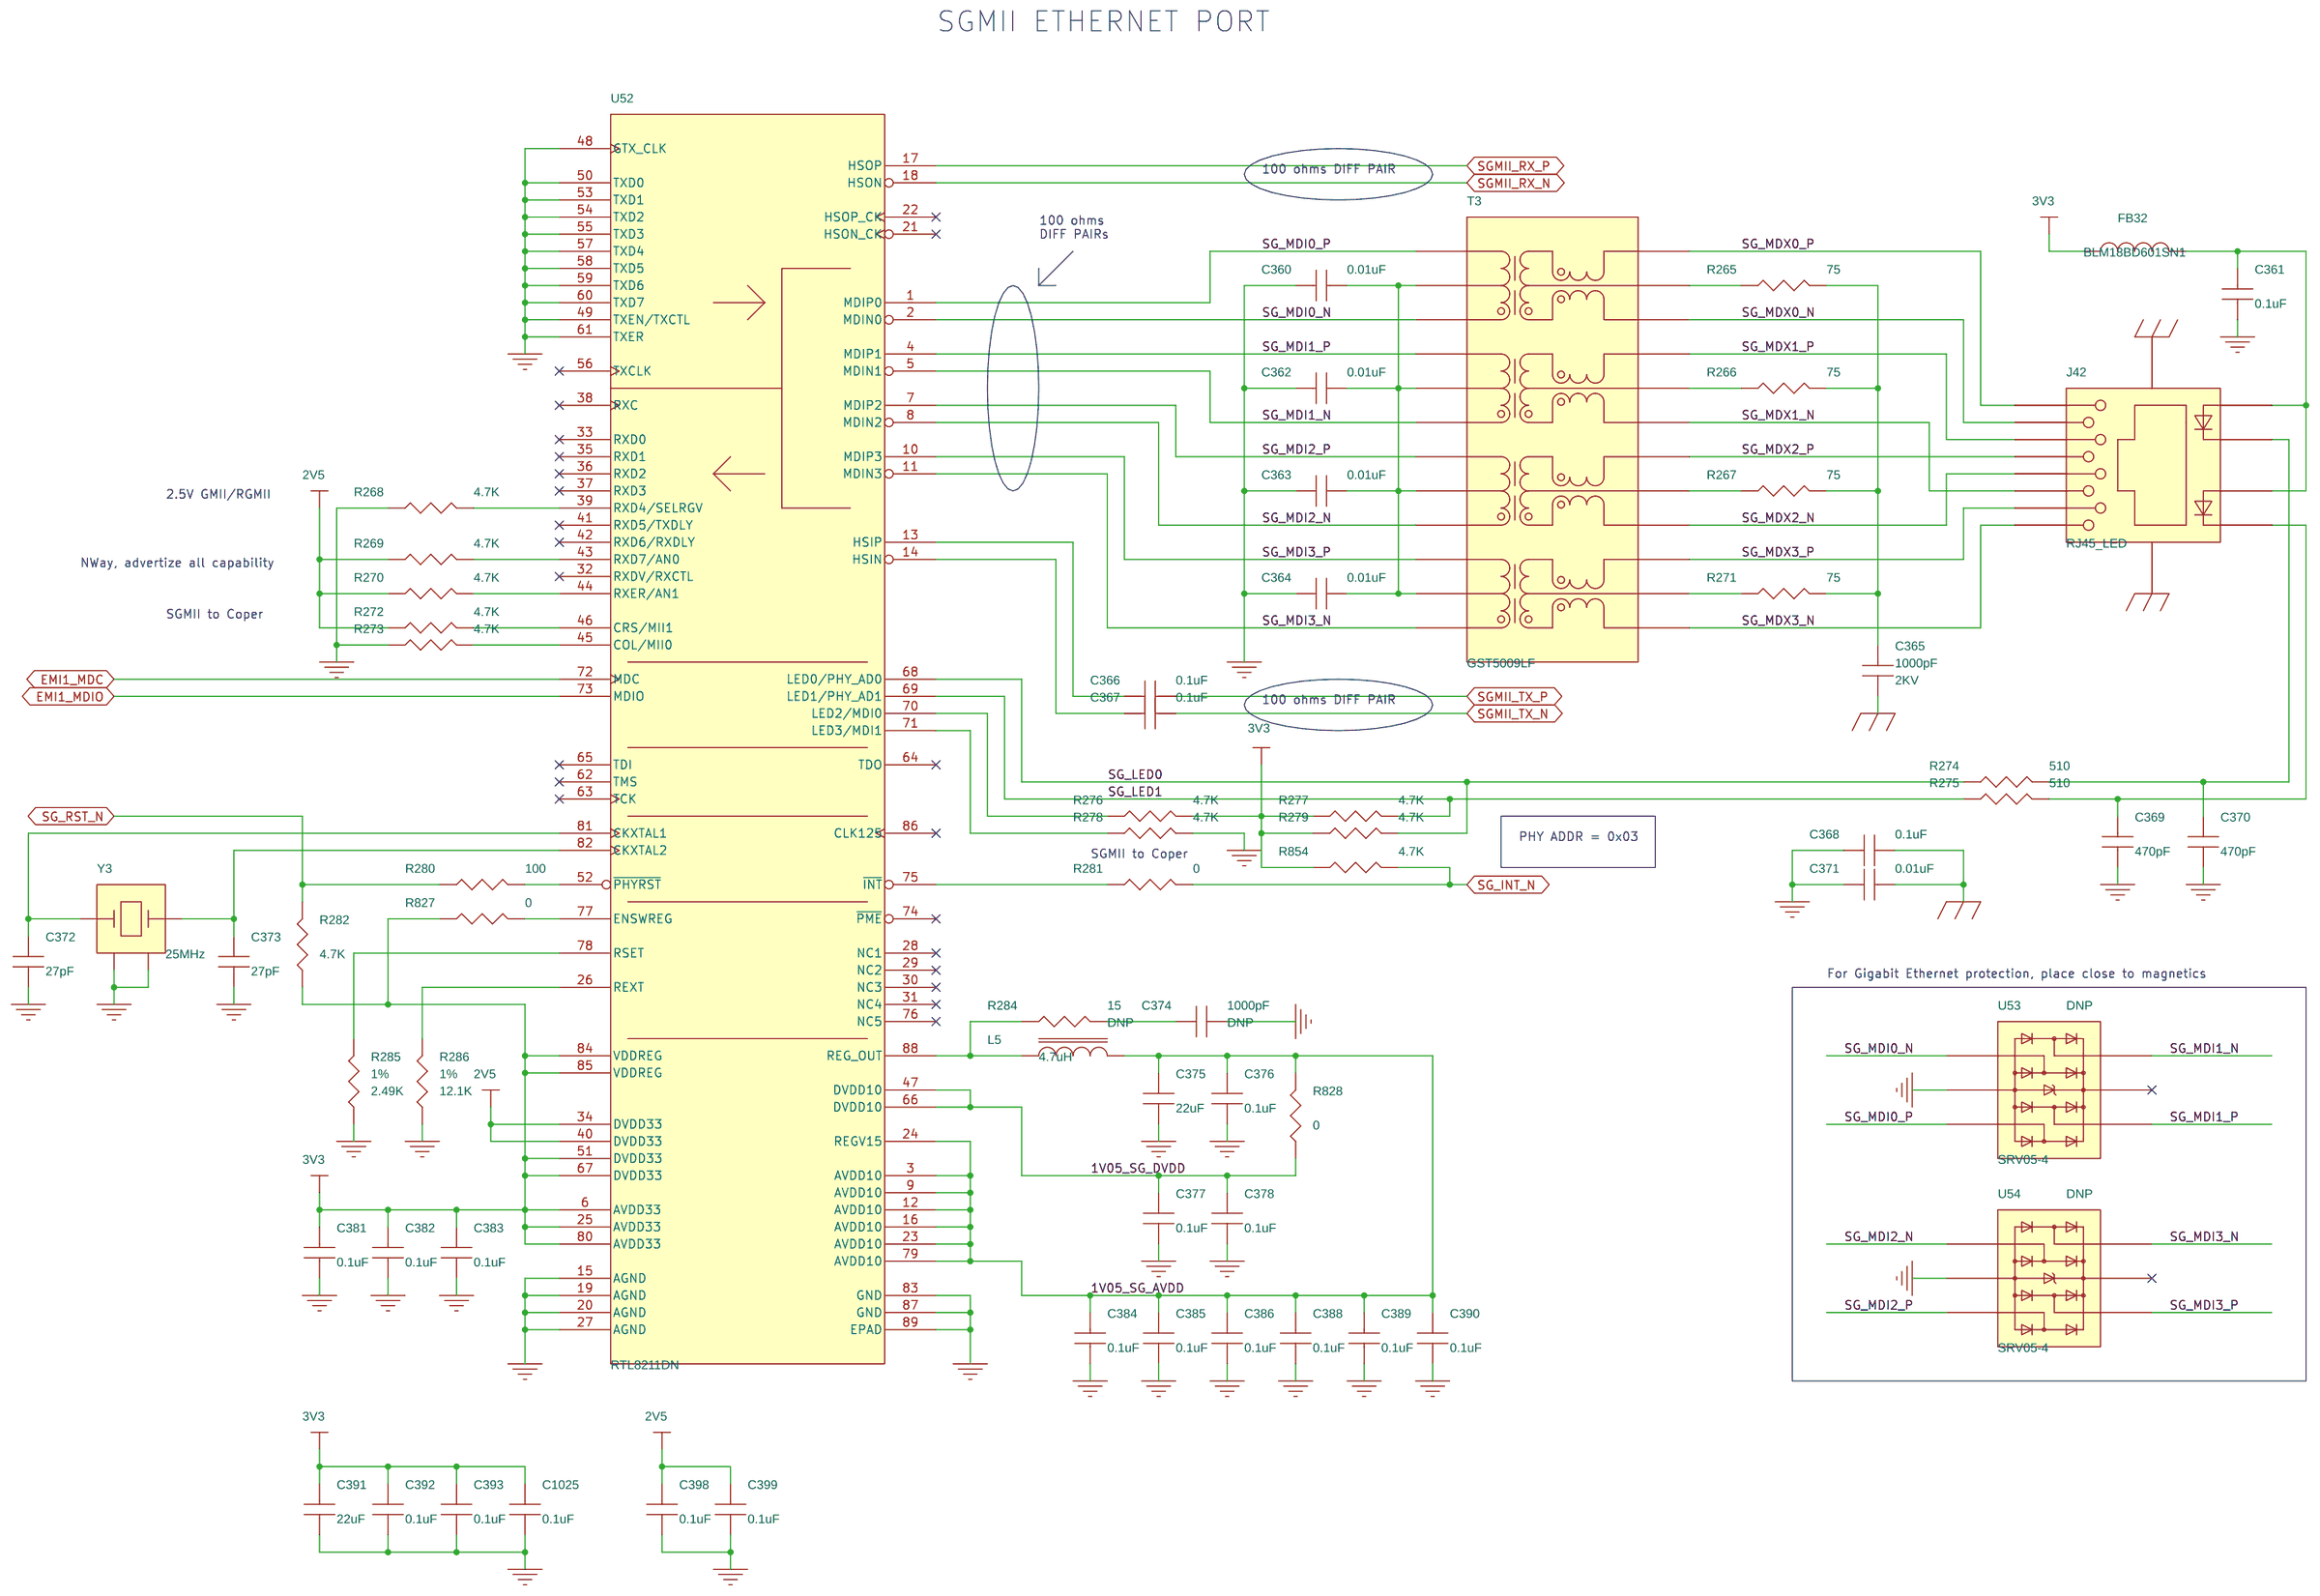
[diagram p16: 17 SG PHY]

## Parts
sheet 08 EC&SD
U1  T1040  [bga_p080_780]  (sections A,B,C,D,E,F,G,H,I,J,K,L,M,N,O)
sheet 10 QE
C84  0.1uF  [0603]
C85  0.01uF  [0402]
C92  10uF  [0603]
C93  0.1uF  [0402]
C94  0.1uF  [0402]
C1080  220uF  [cape_b8]
C1081  0.1uF  [0402]
J43  CONN_2X20  [con_mec6_120]
Q41  IRLML6346  [sot23]
R849  4.7K  [0402]
R850  4.7K  [0402]
R851  4.7K  [0402]
R852  4.7K  [0402]
R859  4.7K  [0402]
R860  1K  [0402]
R867  51  [0402]
R868  33  [0402]
R869  51  [0402]
U100  74LVC1G32  [sc70_5]
U101  74LVC1G32  [sc70_5]
sheet 11 USB
C124  100uF  [7343]
C125  10uF  [0805]
C126  1000pF  [0402]
C127  100uF  [7343]
C128  10uF  [0805]
C129  1000pF  [0402]
C130  10uF  [0805]
C131  0.1uF  [0402]
C132  10pF  [0402]
C133  0.1uF  [0402]
C134  0.01uF  [0402]
C135  1uF  [0402]
C136  0.1uF  [0402]
C1022  0.1uF  [0402]
D3  CMHD3595  [sod123]
D4  CMHD3595  [sod123]
FB6  BLM21PG121SN1  [0805]
FB7  BLM21PG121SN1  [0805]
FB8  BLM21PG121SN1  [0805]
FB9  BLM21PG121SN1  [0805]
FB10  BLM18BD601SN1  [0603]
J41  USB_A_2  [con_usb_a_2]
L1  90ohm  [ind_cm_2012]
L2  90ohm  [ind_cm_2012]
Q3  IRLML6346  [sot23]
Q4  IRLML6346  [sot23]
R155  10K  [0402]
R156  10K  [0402]
R157  0  [0402]
R158  10K  [0402]
R159  10K  [0402]
R160  0  [0402]
R161  1K  [0402]
R162  1K  [0402]
R163  51.1K  [0402]
R164  51.1K  [0402]
R165  18.2K  [0402]
R166  18.2K  [0402]
R167  0  [0402]
R168  0  [0402]
R169  0  [0402]
R170  0  [0402]
R171  10K  [0402]
R172  49.9  [0402]
R173  49.9  [0402]
R174  1K  [0402]
R175  33  [0402]
R176  1K  [0402]
R814  49.9  [0402]
U37  MIC2506YM  [so_8]
U38  VBUS054B-HSF  [tvs_llp75_6l]
U96  VBUS054B-HSF  [tvs_llp75_6l]
X1  24MHz,+/-50ppm  [osc_7x5_4]
sheet 12 Proc Pwr
C137  10uF  [0603]
C138  2.2uF  [0402]
C139  0.01uF  [0402]
C140  10uF  [0603]
C141  10uF  [0603]
C142  10uF  [0603]
C143  10uF  [0603]
C144  10uF  [0603]
C145  10uF  [0603]
C146  10uF  [0603]
C147  0.1uF  [0201]
C148  0.1uF  [0201]
C149  2.2uF  [0402]
C150  0.1uF  [0402]
C151  0.1uF  [0402]
C152  0.1uF  [0402]
C153  0.1uF  [0402]
C154  0.1uF  [0402]
C155  0.1uF  [0402]
C156  0.1uF  [0402]
C157  0.1uF  [0402]
C158  0.1uF  [0201]
C159  0.1uF  [0201]
C160  3000pF  [0402]
C161  2.2uF  [0402]
C162  2.2uF  [0402]
C163  0.01uF  [0402]
C164  0.01uF  [0402]
C165  0.01uF  [0402]
C166  0.01uF  [0402]
C167  0.01uF  [0402]
C168  0.01uF  [0402]
C169  0.01uF  [0402]
C170  0.1uF  [0201]
C171  0.1uF  [0201]
C172  3000pF  [0402]
C173  2.2uF  [0402]
C174  2.2uF  [0402]
C175  10uF  [0603]
C176  0.1uF  [0201]
C177  0.1uF  [0201]
C178  10uF  [0603]
C179  0.1uF  [0201]
C180  0.1uF  [0201]
C181  10uF  [0603]
C182  0.1uF  [0201]
C183  0.1uF  [0201]
C184  0.1uF  [0201]
C185  0.1uF  [0201]
C186  22uF  [0603]
C187  22uF  [0603]
C188  22uF  [0603]
C189  22uF  [0603]
C192  0.1uF  [0201]
C195  10uF  [0603]
C196  0.1uF  [0201]
C197  0.1uF  [0201]
C198  0.1uF  [0201]
C199  0.1uF  [0201]
C200  0.1uF  [0201]
C201  0.1uF  [0201]
C202  0.1uF  [0201]
C203  0.1uF  [0201]
C204  0.1uF  [0201]
C205  0.1uF  [0201]
C206  0.1uF  [0201]
C207  0.1uF  [0201]
C208  0.1uF  [0201]
C209  10uF  [0603]
C210  0.1uF  [0201]
C211  0.1uF  [0201]
C212  0.1uF  [0201]
C213  0.1uF  [0201]
C214  0.1uF  [0201]
C215  0.1uF  [0201]
C216  0.1uF  [0201]
C217  0.1uF  [0201]
C218  0.1uF  [0201]
C219  0.1uF  [0201]
C220  0.1uF  [0201]
C222  0.1uF  [0201]
C223  0.1uF  [0201]
C224  0.1uF  [0201]
C225  0.1uF  [0201]
C226  0.1uF  [0201]
C227  1500pF  [0201]
C228  1500pF  [0201]
C229  1500pF  [0201]
C230  1500pF  [0201]
C232  0.1uF  [0201]
C234  22uF  [0603]
C235  22uF  [0603]
C236  22uF  [0603]
C237  22uF  [0603]
C238  1uF  [0402]
C239  1uF  [0402]
C240  1uF  [0402]
C241  1uF  [0402]
C242  2.2uF  [0402]
C243  2.2uF  [0402]
C244  3000pF  [0402]
C245  0.1uF  [0201]
C246  0.1uF  [0201]
C247  0.1uF  [0201]
C248  0.1uF  [0201]
C249  2.2uF  [0402]
C250  2.2uF  [0402]
C251  3000pF  [0402]
C252  0.1uF  [0201]
C253  0.1uF  [0201]
C254  0.1uF  [0201]
C255  0.1uF  [0201]
C256  0.1uF  [0201]
C904  22uF  [0603]
C905  22uF  [0603]
C906  22uF  [0603]
C907  22uF  [0603]
C908  22uF  [0603]
C909  22uF  [0603]
C910  22uF  [0603]
C911  22uF  [0603]
C912  1uF  [0402]
C913  1uF  [0402]
C914  1uF  [0402]
C915  1uF  [0402]
C916  0.1uF  [0201]
C917  0.1uF  [0201]
C918  0.1uF  [0201]
C919  0.1uF  [0201]
C920  1500pF  [0201]
C921  1500pF  [0201]
C922  1500pF  [0201]
C923  1500pF  [0201]
C1003  1500pF  [0201]
C1004  1500pF  [0201]
C1005  1500pF  [0201]
C1006  1500pF  [0201]
C1007  1500pF  [0201]
C1008  1500pF  [0201]
C1009  1500pF  [0201]
C1010  1500pF  [0201]
C1011  0.1uF  [0201]
C1012  0.1uF  [0201]
C1013  NFM21PC225B0J3  [nfm21]
C1014  NFM21PC225B0J3  [nfm21]
C1026  0.1uF  [0201]
C1027  0.1uF  [0201]
C1028  0.1uF  [0201]
C1029  0.1uF  [0201]
C1030  0.1uF  [0201]
C1031  0.1uF  [0201]
C1032  0.1uF  [0201]
C1033  0.1uF  [0201]
C1034  0.1uF  [0201]
C1035  0.1uF  [0201]
C1036  0.1uF  [0201]
C1037  0.1uF  [0201]
C1038  0.1uF  [0201]
C1039  0.1uF  [0201]
C1106  22uF  [0603]
C1107  22uF  [0603]
C1108  22uF  [0603]
C1109  22uF  [0603]
C1110  22uF  [0603]
C1111  22uF  [0603]
FB11  BLM18PG121SN1  [0603]
FB12  BLM18PG121SN1  [0603]
FB13  BLM18PG121SN1  [0603]
J9  JMP2  [jmp_p254_t_1x2]
J10  JMP2  [jmp_p254_t_1x2]
J11  JMP2  [jmp_p254_t_1x2]
R177  330  [0402]
R178  330  [0402]
R179  330  [0402]
R180  0  [0805]
R182  0  [0805]
R183  0  [0805]
R184  0  [0805]
sheet 13 Proc Gnd
C257  10uF  [0603]
C258  1uF  [0402]
C259  3000pF  [0402]
C260  4.7uF  [0603]
C261  47uF  [0805]
C262  10uF  [0603]
C263  1uF  [0402]
C264  3000pF  [0402]
C265  4.7uF  [0603]
C266  47uF  [0805]
C267  10uF  [0603]
C268  1uF  [0402]
C269  10uF  [0603]
C270  1uF  [0402]
D5  GRN  [led_0603]
D6  GRN  [led_0603]
R185  4.7K  [0402]
R186  510  [0402]
R187  510  [0402]
R188  5.1  [0402]
R189  0.33  [0402]
R190  0  [0402]
R191  5.1  [0402]
R192  0.33  [0402]
R193  0  [0402]
R194  5.1  [0402]
R195  5.1  [0402]
sheet 14 UART&I2C
C271  0.1uF  [0402]
C272  0.1uF  [0402]
C273  0.1uF  [0402]
C274  0.1uF  [0402]
C275  0.1uF  [0402]
C276  100pF  [0402]
C277  100pF  [0402]
C278  100pF  [0402]
C279  100pF  [0402]
C280  0.1uF  [0402]
C281  0.1uF  [0402]
C282  0.1uF  [0402]
C283  0.1uF  [0402]
C284  0.1uF  [0402]
C285  0.1uF  [0402]
C286  0.1uF  [0402]
C287  0.1uF  [0402]
C288  0.1uF  [0402]
C289  100pF  [0402]
C290  100pF  [0402]
C291  100pF  [0402]
C292  100pF  [0402]
C293  0.1uF  [0402]
C294  1000pF  [0402]
C295  0.1uF  [0402]
FB18  BLM18BD601SN1  [0603]
FB19  BLM18BD601SN1  [0603]
FB20  BLM18BD601SN1  [0603]
FB21  BLM18BD601SN1  [0603]
FB22  BLM18BD601SN1  [0603]
FB23  BLM18BD601SN1  [0603]
FB24  BLM18BD601SN1  [0603]
FB25  BLM18BD601SN1  [0603]
J13  RJ45_2X1  [con_rj45_2x1]  (sections A,B)
R196  100  [0402]
R197  100  [0402]
R198  100  [0402]
R199  100  [0402]
R200  100  [0402]
R201  100  [0402]
R202  100  [0402]
R203  100  [0402]
R204  4.7K  [0402]
R205  100  [0402]
R206  100  [0402]
R853  4.7K  [0402]
U39  MAX3232  [tssop_16]
U40  TXBN0304RSV  [qfn_p040_d040_b260x180_16]
U41  MAX3232  [tssop_16]
U42  TXBN0304RSV  [qfn_p040_d040_b260x180_16]
U43  LCDA15C-8  [so_16]
U44  AT24C256  [so_8]
U45  ADT7461  [msop_8]
sheet 15 EC1 PHY
C328  0.01uF  [0402]
C329  0.1uF  [0402]
C330  0.01uF  [0402]
C331  10pF  [0402]
C332  0.01uF  [0402]
C333  0.01uF  [0402]
C334  1000pF  [1206]
C335  10pF  [0402]
C336  0.1uF  [0402]
C337  470pF  [0402]
C338  470pF  [0402]
C339  27pF  [0402]
C340  27pF  [0402]
C341  1000pF  [0402]
C342  0.01uF  [0402]
C343  4.7uF  [0603]
C344  0.1uF  [0402]
C346  0.1uF  [0402]
C347  0.1uF  [0402]
C348  0.1uF  [0402]
C349  0.1uF  [0402]
C350  0.1uF  [0402]
C351  0.1uF  [0402]
C353  0.1uF  [0402]
C354  0.1uF  [0402]
C355  0.1uF  [0402]
C356  4.7uF  [0603]
C357  0.1uF  [0402]
C358  0.1uF  [0402]
FB29  BLM18BD601SN1  [0603]
J14  RJ45_LED_2X1  [con_rj45_2x1_led]  (sections A,B)
L4  2.2uH  [ind_swpa2520]
R236  75  [0603]
R237  75  [0603]
R238  33  [0402]
R239  33  [0402]
R240  75  [0603]
R241  75  [0603]
R242  33  [0402]
R243  33  [0402]
R244  33  [0402]
R245  33  [0402]
R246  33  [0402]
R247  510  [0402]
R248  510  [0402]
R249  100  [0402]
R250  0  [0402]
R251  0  [0402]
R252  4.7K  [0402]
R253  15  [0402]
R256  2.49K  [0402]
R257  4.7K  [0402]
R258  4.7K  [0402]
R259  4.7K  [0402]
R260  4.7K  [0402]
R261  4.7K  [0402]
R262  4.7K  [0402]
R263  4.7K  [0402]
R264  4.7K  [0402]
R825  0  [0402]
R826  0  [0402]
T2  GST5009LF  [mag_gst5009]
U49  RTL8211E-VB  [qfn_p040_d040_b600_48_e440]
U50  SRV05-4  [sot23_6]
U51  SRV05-4  [sot23_6]
Y2  25MHz  [cry_32x25_4]
sheet 16 EC2 PHY
C296  0.01uF  [0402]
C297  0.1uF  [0402]
C298  0.01uF  [0402]
C299  0.01uF  [0402]
C300  10pF  [0402]
C301  0.01uF  [0402]
C302  1000pF  [1206]
C303  10pF  [0402]
C304  27pF  [0402]
C305  27pF  [0402]
C306  0.1uF  [0402]
C307  470pF  [0402]
C308  470pF  [0402]
C309  1000pF  [0402]
C310  0.01uF  [0402]
C312  4.7uF  [0603]
C313  0.1uF  [0402]
C314  0.1uF  [0402]
C315  0.1uF  [0402]
C316  0.1uF  [0402]
C317  0.1uF  [0402]
C319  0.1uF  [0402]
C320  0.1uF  [0402]
C321  0.1uF  [0402]
C322  0.1uF  [0402]
C323  0.1uF  [0402]
C324  4.7uF  [0603]
C325  0.1uF  [0402]
C326  0.1uF  [0402]
FB26  BLM18BD601SN1  [0603]
L3  2.2uH  [ind_swpa2520]
R207  75  [0603]
R208  75  [0603]
R209  33  [0402]
R210  75  [0603]
R211  33  [0402]
R212  75  [0603]
R213  33  [0402]
R214  33  [0402]
R215  33  [0402]
R216  33  [0402]
R217  33  [0402]
R218  510  [0402]
R219  510  [0402]
R220  100  [0402]
R221  0  [0402]
R222  0  [0402]
R224  15  [0402]
R227  2.49K  [0402]
R228  4.7K  [0402]
R229  4.7K  [0402]
R230  4.7K  [0402]
R231  4.7K  [0402]
R232  4.7K  [0402]
R233  4.7K  [0402]
R234  4.7K  [0402]
R235  4.7K  [0402]
R822  0  [0402]
R823  4.7K  [0402]
R824  0  [0402]
T1  GST5009LF  [mag_gst5009]
U46  RTL8211E-VB  [qfn_p040_d040_b600_48_e440]
U47  SRV05-4  [sot23_6]
U48  SRV05-4  [sot23_6]
Y1  25MHz  [cry_32x25_4]
sheet 17 SG PHY
C360  0.01uF  [0402]
C361  0.1uF  [0402]
C362  0.01uF  [0402]
C363  0.01uF  [0402]
C364  0.01uF  [0402]
C365  1000pF  [1206]
C366  0.1uF  [0402]
C367  0.1uF  [0402]
C368  0.1uF  [0402]
C369  470pF  [0402]
C370  470pF  [0402]
C371  0.01uF  [0402]
C372  27pF  [0402]
C373  27pF  [0402]
C374  1000pF  [0402]
C375  22uF  [0805]
C376  0.1uF  [0402]
C377  0.1uF  [0402]
C378  0.1uF  [0402]
C381  0.1uF  [0402]
C382  0.1uF  [0402]
C383  0.1uF  [0402]
C384  0.1uF  [0402]
C385  0.1uF  [0402]
C386  0.1uF  [0402]
C388  0.1uF  [0402]
C389  0.1uF  [0402]
C390  0.1uF  [0402]
C391  22uF  [0805]
C392  0.1uF  [0402]
C393  0.1uF  [0402]
C398  0.1uF  [0402]
C399  0.1uF  [0402]
C1025  0.1uF  [0402]
FB32  BLM18BD601SN1  [0603]
J42  RJ45_LED  [con_rj45_up_1x1_led]
L5  4.7uH  [ind_swpa2520]
R265  75  [0603]
R266  75  [0603]
R267  75  [0603]
R268  4.7K  [0402]
R269  4.7K  [0402]
R270  4.7K  [0402]
R271  75  [0603]
R272  4.7K  [0402]
R273  4.7K  [0402]
R274  510  [0402]
R275  510  [0402]
R276  4.7K  [0402]
R277  4.7K  [0402]
R278  4.7K  [0402]
R279  4.7K  [0402]
R280  100  [0402]
R281  0  [0402]
R282  4.7K  [0402]
R284  15  [0402]
R285  2.49K  [0402]
R286  12.1K  [0402]
R827  0  [0402]
R828  0  [0402]
R854  4.7K  [0402]
T3  GST5009LF  [mag_gst5009]
U52  RTL8211DN  [qfn_p040_d040_b1000_88_e600]
U53  SRV05-4  [sot23_6]
U54  SRV05-4  [sot23_6]
Y3  25MHz  [cry_32x25_4]

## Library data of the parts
U1 = T1040: TYPE: IC; Vendor: Freescale
C84 C85 C134 C139 C163-C169 C227-C230 C296 C298 C299 C301 C310 C328 C330 C332 C333 C342 C360 C362-C364 C371 C920 C921 C1003-C1009 = CAP: VOLTAGE: 25V
C92 C135 C137 C140-C148 C158 C159 C170 C171 C175-C185 C192 C195-C220 C222-C226 C232 C245-C248 C252-C258 C260-C263 C265-C270 C312 C324 C343 C356 C375 C391 C916-C918 C1011 C1012 C1026-C1039 = CAP: VOLTAGE: 6.3V
C93 C94 C125 C128 C130 C131 C133 C136 C150-C157 C271-C275 C280-C288 C293 C295 C297 C306 C313-C317 C319-C323 C325 C326 C329 C336 C344 C346-C351 C353-C355 C357 C358 C361 C366-C368 C376-C378 C381-C386 C388-C390 C392 C393 C398 C399 C1025 C1081 = CAP: VOLTAGE: 16V
C1080 = CAP_E: TYPE: CAP; VOLTAGE: 25V
J43 = CONN_2X20: MPN: MEC6-120-02-S-DV-A-K-TR; TYPE: CON; Vendor: Samtec
Q3 Q4 Q41 = NMOS: MPN: IRLML6346TRPBF; TYPE: MOS; Vendor: IR
R155 R156 R158 R159 R161 R162 R174 R175 R177-R179 R185-R188 R190 R191 R193-R222 R228-R252 R257-R282 R822-R828 R849-R854 R859 R860 R867-R869 = RES: TOL: 5%
U100 U101 = 74LVC1G32: MPN: SN74LVC1G32DCKR; TYPE: IC; Vendor: TI
C124 C127 = CAP_E: TYPE: CAP; VOLTAGE: 10V
C126 C129 C160 C172 C244 C251 C259 C264 C276-C279 C289-C292 C294 C304 C305 C307 C308 C337-C340 C369 C370 C372 C373 = CAP: VOLTAGE: 50V
C132 C300 C303 C309 C331 C335 C341 C374 = CAP: BOM_IGNORE: DNP; VOLTAGE: 50V
C1022 = CAP: BOM_IGNORE: DNP; VOLTAGE: 16V
D3 D4 = DIODE: Vendor: Central
FB6-FB13 FB18-FB26 FB29 FB32 = BEAD: Vendor: Murata
J41 = USB_A_2: MPN: XUSB-6-7-4-3-1-3-05; TYPE: CON; Vendor: XMULTIPLE
L1 L2 = IND_CM: MPN: DLW21HN900SQ2L; TYPE: IND; Vendor: Murata
R157 R160 R167-R170 R176 R224 R284 = RES: BOM_IGNORE: DNP; TOL: 5%
R163-R166 R171-R173 R189 R192 R227 R256 R285 R286 = RES: TOL: 1%
R814 = RES: BOM_IGNORE: DNP; TOL: 1%
U37 = MIC2506: TYPE: IC; Vendor: Micrel
U38 U96 = SRV05-4: MPN: VBUS054B-HSF-GS08; TYPE: IC; Vendor: Vishay
X1 = OSC: MPN: 5x7mm,1.8V,+/-50ppm
C138 C149 C161 C162 C173 C174 C186-C189 C234-C237 C242 C243 C249 C250 C904-C911 C1106-C1111 = CAP: VOLTAGE: 4V
C238-C241 C912-C915 C919 = CAP: BOM_IGNORE: DNP; VOLTAGE: 6.3V
C922 C923 C1010 = CAP: BOM_IGNORE: DNP; VOLTAGE: 25V
C1013 C1014 = CAP_3T_4P: TYPE: CAP; Vendor: Murata
J9-J11 = JMP2: MPN: TSW-102-07-F-S; TYPE: CON; Vendor: Samtec
R180 R183 = RES: BOM_IGNORE: VIT; TOL: 5%
R182 R184 = RES: BOM_IGNORE: VNIT; TOL: 5%
D5 D6 = LED: MPN: 0603,Green
J13 = RJ45_2X1: MPN: 10118069-500B010LF; TYPE: CON; Vendor: FCI
U39 U41 = MAX3232: MPN: MAX3232IPW; TYPE: IC; Vendor: TI
U40 U42 = TXBN0304RSV: MPN: TXBN0304RSVR; TYPE: IC; Vendor: TI
U43 = LCDA15C-8: BOM_IGNORE: DNP; MPN: LCDA15C-8.TBT; TYPE: IC; Vendor: Semtech
U44 = EEPROM-I2C: MPN: AT24C256C-SSHL-B; TYPE: IC; Vendor: Atmel
U45 = ADT7461: MPN: ADT7461ARMZ-R7; TYPE: IC; Vendor: ON Semi
C302 C334 C365 = CAP: VOLTAGE: 2KV
J14 = RJ45_LED_2X1: MPN: 10118075-510B010LF; TYPE: CON; Vendor: FCI
L3 L4 = IND_IRON: MPN: SWPA252012S2R2MT; TYPE: IND; Vendor: Sunlord
R253 = RES: BOM_IGNORE: DNP; VOLTAGE: 50V
T1-T3 = H5004: TYPE: XFMR; Vendor: Bothhand
U46 U49 = RTL8211E-VB: MPN: RTL8211E-VB-CG; TYPE: IC; Vendor: Realtek
U47 U48 U50 U51 U53 U54 = SRV05-4: BOM_IGNORE: DNP; MPN: SRV05-4.TCT; TYPE: IC; Vendor: Semtech
Y1-Y3 = CRYSTAL_4PIN_v2: MPN: 3.2x2.5mm,+/-20ppm; TYPE: XTAL
J42 = RJ45_LED: MPN: 133745; TYPE: CON; Vendor: ERNI
L5 = IND_IRON: MPN: SWPA252012S4R7MT; TYPE: IND; Vendor: Sunlord
U52 = RTL8211DN: MPN: RTL8211DN-VB-GR; TYPE: IC; Vendor: Realtek

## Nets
1V0_FA_VL: C222.1 J11.1 R179.2 U1.G18(FA_VL)
1V0_LP: C256.1 U1.P6(VDD_LP) ; also on sheet 32
1V0_USB_SVDD: C138.1 C147.1 C148.1 C149.1 FB11.1 U1.K9(USB_SVDD1) U1.K10(USB_SVDD2)
1V0S: C1013.2 ; also on sheet 31
1V05_EC1_AVDD: C343.1 C344.1 C353.1 C354.1 C355.1 L4.2 R826.2 U49.3(AVDD10) U49.9(AVDD10) U49.40(AVDD10)
1V05_EC1_DVDD: C348.1 C349.1 R826.1 U49.28(DVDD10) U49.36(DVDD10)
1V05_EC2_AVDD: C312.1 C313.1 C321.1 C322.1 C323.1 L3.2 R824.2 U46.3(AVDD10) U46.9(AVDD10) U46.40(AVDD10)
1V05_EC2_DVDD: C316.1 C317.1 R824.1 U46.28(DVDD10) U46.36(DVDD10)
1V05_SG_AVDD: C375.1 C376.1 C384.1 C385.1 C386.1 C388.1 C389.1 C390.1 L5.2 R828.2 U52.3(AVDD10) U52.9(AVDD10) U52.12(AVDD10) U52.16(AVDD10) U52.23(AVDD10) U52.24(REGV15) U52.79(AVDD10)
1V05_SG_DVDD: C377.1 C378.1 R828.1 U52.47(DVDD10) U52.66(DVDD10)
1V8: R182.1 ; also on sheet 8 21 31
1V8_MTR: C208.1 J10.1 R178.2 U1.F11(PROG_MTR)
1V8_SFP: C192.1 J9.1 R177.2 U1.F12(PROG_SFP)
1V8_SLP: R184.1 ; also on sheet 26 27 30 31
1V8_USB_OVDD: C170.1 C171.1 C172.1 C173.1 C174.1 FB13.1 U1.J9(USB_OVDD1) U1.J10(USB_OVDD2)
1V35: C1014.1 R189.2 R192.2 ; also on sheet 31
1V35_SLP: C137.1 C139.1 C140.1 C141.1 C142.1 C143.1 C144.1 C145.1 C146.1 C150.1 C151.1 C152.1 C153.1 C154.1 C155.1 C156.1 C157.1 C163.1 C164.1 C165.1 C166.1 C167.1 C168.1 C169.1 U1.AA27(G1VDD17) U1.AD27(G1VDD18) U1.AF27(G1VDD19) U1.D27(G1VDD01) U1.F27(G1VDD02) U1.H27(G1VDD03) U1.K21(G1VDD04) U1.K27(G1VDD05) U1.L21(G1VDD06) U1.M21(G1VDD07) U1.M27(G1VDD08) U1.N21(G1VDD09) U1.P21(G1VDD10) U1.P27(G1VDD11) U1.R21(G1VDD12) U1.T21(G1VDD13) U1.U21(G1VDD14) U1.U27(G1VDD15) U1.W27(G1VDD16) ; also on sheet 3 30 31
2V5: C175.1 C176.1 C177.1 C314.1 C315.1 C398.1 C399.1 R229.2 R230.2 R231.2 R269.1 R270.1 R272.1 U1.V8(LVDD1) U1.W8(LVDD2) U46.15(DVDD33) U46.21(DVDD33) U52.34(DVDD33) U52.40(DVDD33) ; also on sheet 8 18 19 20 31
2V5_SLP: C178.1 C179.1 C180.1 C346.1 C347.1 R258.2 R259.2 R260.2 U1.T8(L1VDD1) U1.U8(L1VDD2) U49.15(DVDD33) U49.21(DVDD33) ; also on sheet 7 8 30 31
3V3: C92.1 C93.1 C94.1 C272.1 C281.1 C283.1 C286.1 C293.1 C295.1 C319.1 C320.1 C324.1 C325.1 C326.1 C381.1 C382.1 C383.1 C391.1 C392.1 C393.1 C1025.1 C1081.1 FB26.1 FB32.1 J43.10 J43.12 J43.14 J43.16 R180.1 R204.2 R234.2 R235.2 R276.2 R277.1 R279.1 R282.1 R822.1 R823.1 R827.1 R849.1 R850.1 R851.1 R852.1 R853.2 R854.1 R859.1 U39.16(VCC) U40.13(VCCB) U41.16(VCC) U42.13(VCCB) U44.8(VCC) U45.1(VDD) U46.6(AVDD33) U46.37(DVDD33) U46.41(AVDD33) U46.44(VDDREG) U46.45(VDDREG) U52.6(AVDD33) U52.25(AVDD33) U52.51(DVDD33) U52.67(DVDD33) U52.80(AVDD33) U52.84(VDDREG) U52.85(VDDREG) U100.5(VCC) U101.5(VCC) ; also on sheet 3 5 6 7 9 21 22 23 24 28 29 31 32
3V3_SLP: C350.1 C351.1 C356.1 C357.1 C358.1 D5.2 D6.2 FB12.2 FB29.1 R155.2 R156.2 R158.2 R159.2 R183.1 R185.2 R252.1 R262.2 R264.2 R825.1 U49.6(AVDD33) U49.37(DVDD33) U49.41(AVDD33) U49.44(VDDREG) U49.45(VDDREG) ; also on sheet 7 26 29 30 31 32
3V3_USB_HVDD: C158.1 C159.1 C160.1 C161.1 C162.1 FB12.1 U1.J8(USB_HVDD1) U1.K8(USB_HVDD2)
5V0_SLP: C130.1 C131.1 U37.7(IN) ; also on sheet 29 30 32
5V0_USB1: C127.1 C128.1 C129.1 D4.1 FB6.2 R164.2 U37.8(OUTA)
5V0_USB2: C124.1 C125.1 C126.1 D3.1 FB8.2 R163.2 U37.5(OUTB)
12V: C84.1 C85.1 C1080.1 J43.2 J43.4 J43.6 ; also on sheet 22 25 31 32
AGND_SD1_PLL1: C259.2 C260.2 C261.2 R190.1 U1.AA16(AGND_SD1_PLL1)
AGND_SD1_PLL2: C264.2 C265.2 C266.2 R193.1 U1.AA20(AGND_SD1_PLL2)
AVDD_CGA1: C257.1 C258.1 R188.2 U1.G11(AVDD_CGA1)
AVDD_CGA2: C262.1 C263.1 R191.2 U1.G12(AVDD_CGA2)
AVDD_DDR1: C269.1 C270.1 R195.2 U1.E20(AVDD_D1)
AVDD_PLAT: C267.1 C268.1 R194.2 U1.G10(AVDD_PLAT)
AVDD_SD1_PLL1: C259.1 C260.1 C261.1 R189.1 U1.AB16(AVDD_SD1_PLL1)
AVDD_SD1_PLL2: C264.1 C265.1 C266.1 R192.1 U1.AB20(AVDD_SD1_PLL2)
DVDD: C181.1 C182.1 C183.1 C280.1 C282.1 C1028.1 U1.N8(DVDD1) U1.P8(DVDD2) U1.R8(DVDD3) U40.16(VCCA) U42.16(VCCA) ; also on sheet 7 31
GND: C84.2 C85.2 C92.2 C93.2 C94.2 C124.2 C125.2 C126.2 C127.2 C128.2 C129.2 C130.2 C131.2 C132.2 C133.2 C134.2 C135.2 C136.2 C137.2 C138.2 C139.2 C140.2 C141.2 C142.2 C143.2 C144.2 C145.2 C146.2 C147.2 C148.2 C149.2 C150.2 C151.2 C152.2 C153.2 C154.2 C155.2 C156.2 C157.2 C158.2 C159.2 C160.2 C161.2 C162.2 C163.2 C164.2 C165.2 C166.2 C167.2 C168.2 C169.2 C170.2 C171.2 C172.2 C173.2 C174.2 C175.2 C176.2 C177.2 C178.2 C179.2 C180.2 C181.2 C182.2 C183.2 C184.2 C185.2 C186.2 C187.2 C188.2 C189.2 C192.2 C195.2 C196.2 C197.2 C198.2 C199.2 C200.2 C201.2 C202.2 C203.2 C204.2 C205.2 C206.2 C207.2 C208.2 C209.2 C210.2 C211.2 C212.2 C213.2 C214.2 C215.2 C216.2 C217.2 C218.2 C219.2 C220.2 C222.2 C223.2 C224.2 C225.2 C226.2 C227.2 C228.2 C229.2 C230.2 C232.2 C234.2 C235.2 C236.2 C237.2 C238.2 C239.2 C240.2 C241.2 C242.2 C243.2 C244.2 C245.2 C246.2 C247.2 C248.2 C249.2 C250.2 C251.2 C252.2 C253.2 C254.2 C255.2 C256.2 C257.2 C258.2 C262.2 C263.2 C267.2 C268.2 C269.2 C270.2 C272.2 C273.2 C275.2 C276.2 C277.2 C278.2 C279.2 C280.2 C281.2 C282.2 C283.2 C286.2 C287.2 C288.2 C289.2 C290.2 C291.2 C292.2 C293.2 C295.2 C296.1 C297.2 C298.1 C299.1 C300.1 C301.1 C303.2 C304.2 C305.2 C306.1 C307.2 C308.2 C309.2 C310.1 C312.2 C313.2 C314.2 C315.2 C316.2 C317.2 C319.2 C320.2 C321.2 C322.2 C323.2 C324.2 C325.2 C326.2 C328.1 C329.2 C330.1 C331.1 C332.1 C333.1 C335.2 C336.1 C337.2 C338.2 C339.2 C340.2 C341.2 C342.1 C343.2 C344.2 C346.2 C347.2 C348.2 C349.2 C350.2 C351.2 C353.2 C354.2 C355.2 C356.2 C357.2 C358.2 C360.1 C361.2 C362.1 C363.1 C364.1 C368.1 C369.2 C370.2 C371.1 C372.2 C373.2 C374.2 C375.2 C376.2 C377.2 C378.2 C381.2 C382.2 C383.2 C384.2 C385.2 C386.2 C388.2 C389.2 C390.2 C391.2 C392.2 C393.2 C398.2 C399.2 C904.2 C905.2 C906.2 C907.2 C908.2 C909.2 C910.2 C911.2 C912.2 C913.2 C914.2 C915.2 C916.2 C917.2 C918.2 C919.2 C920.2 C921.2 C922.2 C923.2 C1003.2 C1004.2 C1005.2 C1006.2 C1007.2 C1008.2 C1009.2 C1010.2 C1011.2 C1012.2 C1013.3 C1013.4 C1014.3 C1014.4 C1025.2 C1026.2 C1027.2 C1028.2 C1029.2 C1030.2 C1031.2 C1032.2 C1033.2 C1034.2 C1035.2 C1036.2 C1037.2 C1038.2 C1039.2 C1080.2 C1081.2 C1106.2 C1107.2 C1108.2 C1109.2 C1110.2 C1111.2 FB7.2 FB9.2 J13.A4 J13.A5 J13.B4 J13.B5 J14.A10 J14.B12 J43.5 J43.15 J43.19 J43.23 J43.26 J43.30 J43.37 J43.40 Q3.2(S) Q4.2(S) Q41.2(S) R161.1 R162.1 R165.1 R166.1 R171.1 R172.1 R173.1 R176.1 R177.1 R178.1 R179.1 R190.2 R193.2 R227.1 R228.2 R232.2 R233.2 R256.1 R257.2 R261.2 R263.2 R268.1 R273.1 R278.2 R285.1 R286.1 R814.1 U1.A2(GND001) U1.A20(GND002) U1.A27(GND003) U1.AA11(GND148) U1.AA13(S1GND05) U1.AA15(S1GND06) U1.AA17(S1GND07) U1.AA19(S1GND08) U1.AA21(S1GND09) U1.AA24(GND149) U1.AB2(GND150) U1.AB5(GND151) U1.AB7(GND152) U1.AB13(S1GND10) U1.AB17(S1GND11) U1.AB21(S1GND12) U1.AB22(GND153) U1.AB26(GND154) U1.AC10(X1GND01) U1.AC11(X1GND02) U1.AC13(X1GND03) U1.AC14(X1GND04) U1.AC16(X1GND05) U1.AC17(X1GND06) U1.AC19(X1GND07) U1.AC20(X1GND08) U1.AC24(GND155) U1.AC26(GND156) U1.AD4(GND157) U1.AD6(GND158) U1.AD9(X1GND09) U1.AD12(X1GND10) U1.AD15(X1GND11) U1.AD18(X1GND12) U1.AD21(X1GND13) U1.AD22(GND159) U1.AE2(GND160) U1.AE9(X1GND14) U1.AE12(X1GND15) U1.AE15(X1GND16) U1.AE18(X1GND17) U1.AE21(X1GND18) U1.AE24(GND161) U1.AE26(GND162) U1.AF9(GND163) U1.AF10(S1GND13) U1.AF11(S1GND14) U1.AF12(S1GND15) U1.AF13(S1GND16) U1.AF14(S1GND17) U1.AF15(S1GND18) U1.AF16(S1GND19) U1.AF17(S1GND20) U1.AF18(S1GND21) U1.AF19(S1GND22) U1.AF20(S1GND23) U1.AF21(GND164) U1.AG1(GND165) U1.AG4(GND166) U1.AG6(GND167) U1.AG9(S1GND24) U1.AG12(S1GND25) U1.AG15(S1GND26) U1.AG18(S1GND27) U1.AG21(S1GND28) U1.AG22(GND168) U1.AG23(GND169) U1.AG26(GND170) U1.AH2(GND171) U1.AH9(S1GND29) U1.AH12(S1GND30) U1.AH15(S1GND31) U1.AH18(S1GND32) U1.AH21(S1GND33) U1.B1(GND004) U1.B4(GND005) U1.B7(GND006) U1.B10(GND007) U1.B13(GND008) U1.B16(GND009) U1.B19(GND010) U1.B23(GND011) U1.B25(GND012) U1.B28(GND013) U1.C22(GND014) U1.C26(GND015) U1.D2(GND016) U1.D20(GND017) U1.D21(GND018) U1.D24(GND019) U1.E1(USB_AGND01) U1.E2(USB_AGND02) U1.E3(USB_AGND03) U1.E5(GND020) U1.E7(GND021) U1.E10(GND022) U1.E13(GND023) U1.E16(GND024) U1.E19(GND025) U1.E22(GND026) U1.E26(GND027) U1.F3(USB_AGND04) U1.F15(GND028) U1.F24(GND029) U1.G1(USB_AGND05) U1.G2(USB_AGND06) U1.G3(USB_AGND07) U1.G5(USB_AGND08) U1.G7(GND030) U1.G13(GND031) U1.G16(GND032) U1.G22(GND033) U1.G26(GND034) U1.H3(USB_AGND09) U1.H7(GND035) U1.H8(GND036) U1.H9(GND037) U1.H10(GND038) U1.H11(GND039) U1.H12(GND040) U1.H13(GND041) U1.H14(GND042) U1.H15(GND043) U1.H16(GND044) U1.H17(GND045) U1.H18(GND046) U1.H19(GND047) U1.H20(GND048) U1.H24(GND049) U1.J1(USB_AGND10) U1.J2(USB_AGND11) U1.J3(USB_AGND12) U1.J7(GND050) U1.J22(GND051) U1.J26(GND052) U1.K2(GND053) U1.K5(GND054) U1.K6(GND055) U1.K7(GND056) U1.K12(GND057) U1.K14(GND058) U1.K16(GND059) U1.K18(GND060) U1.K20(GND061) U1.K24(GND062) U1.L7(GND063) U1.L9(GND064) U1.L11(GND065) U1.L13(GND066) U1.L15(GND067) U1.L17(GND068) U1.L19(GND069) U1.L22(GND070) U1.L26(GND071) U1.M7(GND072) U1.M10(GND073) U1.M12(GND074) U1.M14(GND075) U1.M16(GND076) U1.M18(GND077) U1.M20(GND078) U1.M24(GND079) U1.N2(GND080) U1.N5(GND081) U1.N7(GND082) U1.N9(GND083) U1.N11(GND084) U1.N13(GND085) U1.N15(GND086) U1.N17(GND087) U1.N19(GND088) U1.N22(GND089) U1.N26(GND090) U1.P7(GND091) U1.P10(GND092) U1.P12(GND093) U1.P14(GND094) U1.P16(GND095) U1.P18(GND096) U1.P20(GND097) U1.P24(GND098) U1.R7(GND099) U1.R9(GND100) U1.R11(GND101) U1.R13(GND102) U1.R15(GND103) U1.R17(GND104) U1.R19(GND105) U1.R22(GND106) U1.R26(GND107) U1.T2(GND108) U1.T5(GND109) U1.T7(GND110) U1.T10(GND111) U1.T12(GND112) U1.T14(GND113) U1.T16(GND114) U1.T18(GND115) U1.T20(GND116) U1.T22(GND117) U1.T26(GND118) U1.U7(GND119) U1.U9(GND120) U1.U11(GND121) U1.U13(GND122) U1.U15(GND123) U1.U17(GND124) U1.U19(GND125) U1.U24(GND126) U1.V7(GND127) U1.V10(GND128) U1.V12(GND129) U1.V14(GND130) U1.V16(GND131) U1.V18(GND132) U1.V20(GND133) U1.V22(GND134) U1.V26(GND135) U1.W2(GND136) U1.W5(GND137) U1.W7(GND138) U1.W9(GND139) U1.W11(GND140) U1.W13(GND141) U1.W24(GND142) U1.Y7(GND143) U1.Y10(GND144) U1.Y12(GND145) U1.Y14(S1GND01) U1.Y16(S1GND02) U1.Y17(S1GND03) U1.Y18(S1GND04) U1.Y22(GND146) U1.Y26(GND147) U37.6(GND) U38.1 U38.2 U39.15(GND) U40.6(GND) U40.7(GND) U40.8(~{OE}) U41.15(GND) U42.6(GND) U42.7(GND) U42.8(~{OE}) U43.9 U43.10 U43.11 U43.12 U43.13 U43.14 U43.15 U43.16 U44.1(A0) U44.2(A1) U44.3(A2) U44.4(GND) U44.7(WP) U45.5(GND) U46.47(GND) U46.49(EPAD) U47.2 U48.2 U49.47(GND) U49.49(EPAD) U50.2 U51.2 U52.15(AGND) U52.19(AGND) U52.20(AGND) U52.27(AGND) U52.48(GTX_CLK) U52.49(TXEN/TXCTL) U52.50(TXD0) U52.53(TXD1) U52.54(TXD2) U52.55(TXD3) U52.57(TXD4) U52.58(TXD5) U52.59(TXD6) U52.60(TXD7) U52.61(TXER) U52.83(GND) U52.87(GND) U52.89(EPAD) U53.2 U54.2 U96.1 U96.2 U100.3(GND) U101.3(GND) X1.2(GND) Y1.2 Y1.4 Y2.2 Y2.4 Y3.2 Y3.4 ; also on sheet 3 4 5 6 7 8 9 18 19 20 21 22 23 24 25 26 27 28 29 30 31 32 33
SVDD: C242.1 C243.1 C244.1 C245.1 C246.1 C247.1 C248.1 C1013.1 C1027.1 U1.W15(S1VDD1) U1.W16(S1VDD2) U1.W17(S1VDD3) U1.W18(S1VDD4) U1.W19(S1VDD5) U1.W20(S1VDD6) U1.Y13(S1VDD7) ; also on sheet 8
EARTH: C302.2 C306.2 C310.2 C334.2 C336.2 C342.2 C365.2 C368.2 C371.2 J13.17 J13.18 J13.19 J13.20 J13.21 J13.22 J14.25 J14.26 J14.27 J14.28 J41.9 J41.10 J41.11 J41.12 J42.13 J42.14 ; also on sheet 20 21 33
EC1_GTXCLK: U49.22(TXC) ; also on sheet 8
EC1_INT_N: R250.2 ; also on sheet 7
EC1_LED0: R247.1 R262.1 U49.34(LED0/PHY_AD0)
EC1_LED1: R248.1 R263.1 U49.35(LED1/PHY_AD1)
EC1_MDI0_N: T2.11 U49.2(MDI-[0]) U50.1
EC1_MDI0_P: T2.12 U49.1(MDI+[0]) U50.3
EC1_MDI1_N: T2.8 U49.5(MDI-[1]) U50.6
EC1_MDI1_P: T2.9 U49.4(MDI+[1]) U50.4
EC1_MDI2_N: T2.5 U49.8(MDI-[2]) U51.1
EC1_MDI2_P: T2.6 U49.7(MDI+[2]) U51.3
EC1_MDI3_N: T2.2 U49.11(MDI-[3]) U51.6
EC1_MDI3_P: T2.3 U49.10(MDI+[3]) U51.4
EC1_MDX0_N: J14.B2 T2.14
EC1_MDX0_P: J14.B1 T2.13
EC1_MDX1_N: J14.B6 T2.17
EC1_MDX1_P: J14.B3 T2.16
EC1_MDX2_N: J14.B5 T2.20
EC1_MDX2_P: J14.B4 T2.19
EC1_MDX3_N: J14.B8 T2.23
EC1_MDX3_P: J14.B7 T2.22
EC1_PME_N: R251.2 ; also on sheet 7
EC1_REFCLK: R246.2 ; also on sheet 8
EC1_RST_N: R249.1 R252.2 ; also on sheet 26
EC1_RXCLK: R238.1 ; also on sheet 8
EC1_RXCTL: R245.1 R261.1 ; also on sheet 8
EC1_RXD0: R239.1 R257.1 ; also on sheet 8
EC1_RXD1: R242.1 R258.1 ; also on sheet 8
EC1_RXD2: R243.1 R259.1 ; also on sheet 8
EC1_RXD3: R244.1 R260.1 ; also on sheet 8
EC1_RXDLY: R264.1 U49.32(LED2/RXDLY)
EC1_TXCTL: U49.27(TXCTL) ; also on sheet 8
EC1_TXD0: U49.23(TXD0) ; also on sheet 8
EC1_TXD1: U49.24(TXD1) ; also on sheet 8
EC1_TXD2: U49.25(TXD2) ; also on sheet 8
EC1_TXD3: U49.26(TXD3) ; also on sheet 8
EC2_GTXCLK: U46.22(TXC) ; also on sheet 8
EC2_INT_N: R221.2 ; also on sheet 7
EC2_LED0: R218.1 R233.1 U46.34(LED0/PHY_AD0)
EC2_LED1: R219.1 R234.1 U46.35(LED1/PHY_AD1)
EC2_MDI0_N: T1.11 U46.2(MDI-[0]) U47.1
EC2_MDI0_P: T1.12 U46.1(MDI+[0]) U47.3
EC2_MDI1_N: T1.8 U46.5(MDI-[1]) U47.6
EC2_MDI1_P: T1.9 U46.4(MDI+[1]) U47.4
EC2_MDI2_N: T1.5 U46.8(MDI-[2]) U48.1
EC2_MDI2_P: T1.6 U46.7(MDI+[2]) U48.3
EC2_MDI3_N: T1.2 U46.11(MDI-[3]) U48.6
EC2_MDI3_P: T1.3 U46.10(MDI+[3]) U48.4
EC2_MDX0_N: J14.A2 T1.14
EC2_MDX0_P: J14.A1 T1.13
EC2_MDX1_N: J14.A6 T1.17
EC2_MDX1_P: J14.A3 T1.16
EC2_MDX2_N: J14.A5 T1.20
EC2_MDX2_P: J14.A4 T1.19
EC2_MDX3_N: J14.A8 T1.23
EC2_MDX3_P: J14.A7 T1.22
EC2_PME_N: R222.2 ; also on sheet 7
EC2_REFCLK: R217.2 ; also on sheet 8
EC2_RST_N: R220.1 R823.2 ; also on sheet 26
EC2_RXCLK: R211.1 ; also on sheet 8
EC2_RXCTL: R216.1 R232.1 ; also on sheet 8
EC2_RXD0: R209.1 R228.1 ; also on sheet 8
EC2_RXD1: R213.1 R229.1 ; also on sheet 8
EC2_RXD2: R214.1 R230.1 ; also on sheet 8
EC2_RXD3: R215.1 R231.1 ; also on sheet 8
EC2_RXDLY: R235.1 U46.32(LED2/RXDLY)
EC2_TXCTL: U46.27(TXCTL) ; also on sheet 8
EC2_TXD0: U46.23(TXD0) ; also on sheet 8
EC2_TXD1: U46.24(TXD1) ; also on sheet 8
EC2_TXD2: U46.25(TXD2) ; also on sheet 8
EC2_TXD3: U46.26(TXD3) ; also on sheet 8
EMI1_MDC: U46.30(MDC) U52.72(MDC) ; also on sheet 8 18 19
EMI1_MDC_SLP: U49.30(MDC) ; also on sheet 8
EMI1_MDIO: U46.31(MDIO) U52.73(MDIO) ; also on sheet 8 18 19
EMI1_MDIO_SLP: U49.31(MDIO) ; also on sheet 8
EVDD: C185.1 U1.L8(EVDD1) ; also on sheet 6 31
I2C1_SCL: U44.6(SCL) U45.8(SCLK) ; also on sheet 3 7 29
I2C1_SDA: U44.5(SDA) U45.7(SDATA) ; also on sheet 3 7 29
LED_T1040_DET: R186.1 ; also on sheet 26
LED_T2081_DET: R187.1 ; also on sheet 26
OVDD: C184.1 C195.1 C196.1 C197.1 C198.1 C199.1 C232.1 C1011.1 C1012.1 R180.2 R182.2 R188.1 R191.1 U1.G9(TH_VDD) U1.J14(OVDD1) U1.J15(OVDD2) U1.J16(OVDD3) U1.J17(OVDD4) U1.J18(OVDD5) U1.J19(OVDD6) U1.M8(CVDD1) ; also on sheet 4 5 6 7 26 27
OVDD_OSC_USB: C135.1 C136.1 FB10.2 R174.1 X1.4(VDD)
OVDD_SLP: C133.1 C134.1 C209.1 C210.1 C211.1 C220.1 FB10.1 FB13.2 J9.2 J10.2 R183.2 R184.2 R194.1 R195.1 U1.J11(O1VDD1) U1.J12(O1VDD2) U1.J13(O1VDD3) ; also on sheet 7 26 27
PROC_UART1_CTS_N: U40.1(A1) ; also on sheet 7
PROC_UART1_RTS_N: U40.2(A2) ; also on sheet 7
PROC_UART1_RXD: U40.4(A4) ; also on sheet 7
PROC_UART1_TXD: U40.3(A3) ; also on sheet 7
PROC_UART2_CTS_N: U42.1(A1) ; also on sheet 7
PROC_UART2_RTS_N: U42.2(A2) ; also on sheet 7
PROC_UART2_RXD: U42.4(A4) ; also on sheet 7
PROC_UART2_TXD: U42.3(A3) ; also on sheet 7
RS232_CTS1: C276.1 FB21.2 J13.A8 U43.4
RS232_CTS2: C289.1 FB25.2 J13.B8 U43.5
RS232_RTS1: C277.1 FB20.2 J13.A1 U43.2
RS232_RTS2: C290.1 FB24.2 J13.B1 U43.8
RS232_RXD1: C278.1 FB19.2 J13.A6 U43.3
RS232_RXD2: C291.1 FB23.2 J13.B6 U43.6
RS232_TXD1: C279.1 FB18.2 J13.A3 U43.1
RS232_TXD2: C292.1 FB22.2 J13.B3 U43.7
SENSEGND: U1.G20(SENSEGND) ; also on sheet 29
SENSEGNDC: U1.AB10(SENSEGNDC) ; also on sheet 29
SENSEVDD: U1.G19(SENSEVDD) ; also on sheet 29
SENSEVDDC: U1.AB9(SENSEVDDC) ; also on sheet 29
SG_INT_N: R281.2 R854.2 ; also on sheet 26
SG_LED0: R274.1 R279.2 U52.68(LED0/PHY_AD0)
SG_LED1: R275.1 R277.2 U52.69(LED1/PHY_AD1)
SG_MDI0_N: T3.11 U52.2(MDIN0) U53.1
SG_MDI0_P: T3.12 U52.1(MDIP0) U53.3
SG_MDI1_N: T3.8 U52.5(MDIN1) U53.6
SG_MDI1_P: T3.9 U52.4(MDIP1) U53.4
SG_MDI2_N: T3.5 U52.8(MDIN2) U54.1
SG_MDI2_P: T3.6 U52.7(MDIP2) U54.3
SG_MDI3_N: T3.2 U52.11(MDIN3) U54.6
SG_MDI3_P: T3.3 U52.10(MDIP3) U54.4
SG_MDX0_N: J42.2 T3.14
SG_MDX0_P: J42.1 T3.13
SG_MDX1_N: J42.6 T3.17
SG_MDX1_P: J42.3 T3.16
SG_MDX2_N: J42.5 T3.20
SG_MDX2_P: J42.4 T3.19
SG_MDX3_N: J42.8 T3.23
SG_MDX3_P: J42.7 T3.22
SG_RST_N: R280.1 R282.2 ; also on sheet 26
SGMII_RX_N: U52.18(HSON) ; also on sheet 9
SGMII_RX_P: U52.17(HSOP) ; also on sheet 9
SGMII_TX_N: C367.2 ; also on sheet 9
SGMII_TX_P: C366.2 ; also on sheet 9
SPI_CLK: R867.2 ; also on sheet 6 23 24
SPI_CS3_N: U100.1(I0) U101.1(I0) ; also on sheet 6
SPI_CS3_SEL: R860.1 U100.2(I1) ; also on sheet 26
SPI_MISO: R868.2 ; also on sheet 6 23 24
SPI_MOSI: R869.2 ; also on sheet 6 23 24
T2081_DET_N: R185.1 U1.AH27(DEV_DET) ; also on sheet 26
TDMA_RCK_CLK8_12: J43.21 U1.M4(CLK12)
TDMA_RQ: J43.3 U1.R2(TDMA_RQ)
TDMA_RSYNC: J43.11 U1.U1(TDMA_RSYNC)
TDMA_RXD: J43.13 U1.U2(TDMA_RXD)
TDMA_TCK_CLK9: J43.17 U1.P4(CLK09)
TDMA_TSYNC: J43.9 U1.R1(TDMA_TSYNC)
TDMA_TXD: J43.7 U1.T1(TDMA_TXD)
TDMB_RCK_CLK10: J43.29 U1.P3(CLK10)
TDMB_RQ: J43.24 U1.R4(TDMB_RQ)
TDMB_RSYNC: J43.18 U1.T3(TDMB_RSYNC)
TDMB_RXD: J43.1 U1.U4(TDMB_RXD)
TDMB_TCK_CLK11: J43.39 U1.N4(CLK11)
TDMB_TSYNC: J43.22 U1.R3(TDMB_TSYNC)
TDMB_TXD: J43.20 U1.T4(TDMB_TXD)
TDMR1_INT_N: J43.31 R850.2 ; also on sheet 26
TDMR2_INT_N: J43.33 R851.2 ; also on sheet 26
TDMR_PRS_N: J43.27 R849.2 ; also on sheet 26
TDMR_RST_N: J43.35 R852.2 ; also on sheet 26
TDMR_SLP_N: J43.25 ; also on sheet 26
TDMR_SPI_CS0_N: J43.32 U100.4(O)
TDMR_SPI_CS1_N: J43.34 U101.4(O)
TEMP_DIODE_N: R206.1 ; also on sheet 7
TEMP_DIODE_P: R205.1 ; also on sheet 7
THERM_ALERT_N: R853.1 U45.6(~{ALERT}/~{THERM2}) ; also on sheet 26
THERM_FAULT_N: R204.1 U45.4(~{THERM}) ; also on sheet 26 32
UART1_CTS_N: U39.9(R2-OUT) U40.12(B1)
UART1_RTS_N: U39.10(T2-IN) U40.11(B2)
UART1_RXD: U39.12(R1-OUT) U40.9(B4)
UART1_TXD: U39.11(T1-IN) U40.10(B3)
UART2_CTS_N: U41.9(R2-OUT) U42.12(B1)
UART2_RTS_N: U41.10(T2-IN) U42.11(B2)
UART2_RXD: U41.12(R1-OUT) U42.9(B4)
UART2_TXD: U41.11(T1-IN) U42.10(B3)
USB1_DM: J41.6 L1.3 R168.2 U38.4
USB1_DP: J41.7 L1.2 R167.2 U38.6
USB1_FLG_N: Q3.1(G) R157.2 R159.1 U37.2(FLGA)
USB1_PWREN: R162.2 U1.F6(USB1_DRVVBUS) U37.1(CTLA)
USB1_VBUS: FB6.1 J41.5 U38.5
USB1_VBUSCLMP: D4.2 R164.1 R166.2 U1.E4(USB1_VBUSCLMP)
USB2_DM: J41.2 L2.3 R170.2 U96.4
USB2_DP: J41.3 L2.2 R169.2 U96.6
USB2_FLG_N: Q4.1(G) R158.1 R160.2 U37.3(FLGB)
USB2_PWREN: R161.2 U1.J5(USB2_DRVVBUS) U37.4(CTLB)
USB2_VBUS: FB8.1 J41.1 U96.5
USB2_VBUSCLMP: D3.2 R163.1 R165.2 U1.J4(USB2_VBUSCLMP)
USB_REFCLK: R175.2 R176.2 U1.F8(USBCLK)
VCORE: C186.1 C187.1 C188.1 C189.1 C200.1 C201.1 C202.1 C203.1 C204.1 C205.1 C206.1 C207.1 C212.1 C213.1 C214.1 C215.1 C216.1 C217.1 C218.1 C219.1 C223.1 C224.1 C225.1 C226.1 C227.1 C228.1 C229.1 C230.1 C904.1 C905.1 C906.1 C907.1 C908.1 C909.1 C910.1 C911.1 C912.1 C913.1 C914.1 C915.1 C1003.1 C1004.1 C1005.1 C1006.1 C1007.1 C1008.1 C1009.1 C1010.1 C1029.1 C1030.1 C1031.1 C1032.1 C1033.1 C1034.1 C1035.1 C1036.1 C1106.1 C1107.1 C1108.1 C1109.1 C1110.1 C1111.1 J11.2 U1.K15(VDD01) U1.K17(VDD02) U1.K19(VDD03) U1.L12(VDD04) U1.L14(VDD05) U1.L16(VDD06) U1.L18(VDD07) U1.L20(VDD08) U1.M9(VDD09) U1.M13(VDD10) U1.M15(VDD11) U1.M17(VDD12) U1.M19(VDD13) U1.N12(VDD14) U1.N14(VDD15) U1.N16(VDD16) U1.N18(VDD17) U1.N20(VDD18) U1.P9(VDD19) U1.P11(VDD20) U1.P13(VDD21) U1.P15(VDD22) U1.P17(VDD23) U1.P19(VDD24) U1.R12(VDD25) U1.R14(VDD26) U1.R16(VDD27) U1.R18(VDD28) U1.R20(VDD29) U1.T9(VDD30) U1.T13(VDD31) U1.T15(VDD32) U1.T17(VDD33) U1.T19(VDD34) U1.U14(VDD35) U1.U16(VDD36) U1.U18(VDD37) U1.U20(VDD38) U1.V9(VDD39) U1.V13(VDD40) U1.V15(VDD41) U1.V17(VDD42) U1.V19(VDD43) U1.W14(VDD44) U1.Y8(VDD45) U1.Y9(VDD46) U1.Y11(VDD47) ; also on sheet 29 31
VCORE_SLP: C234.1 C235.1 C236.1 C237.1 C238.1 C239.1 C240.1 C241.1 C916.1 C917.1 C918.1 C919.1 C920.1 C921.1 C922.1 C923.1 C1037.1 C1038.1 C1039.1 FB11.2 U1.K11(VDDC01) U1.K13(VDDC02) U1.L10(VDDC03) U1.M11(VDDC04) U1.N10(VDDC05) U1.R10(VDDC06) U1.T11(VDDC07) U1.U10(VDDC08) U1.U12(VDDC09) U1.V11(VDDC10) U1.W10(VDDC11) U1.W12(VDDC12) ; also on sheet 29 31
XVDD: C249.1 C250.1 C251.1 C252.1 C253.1 C254.1 C255.1 C1014.2 C1026.1 U1.AC9(X1VDD1) U1.AC12(X1VDD2) U1.AC15(X1VDD3) U1.AC18(X1VDD4) U1.AC21(X1VDD5) ; also on sheet 8
N16869850: C300.2 R211.2 U46.19(RXC)
N16869910: R209.2 U46.14(RXD0/SELRGV)
N16869938: R213.2 U46.16(RXD1/TXDLY)
N16869959: R214.2 U46.17(RXD2/AN0)
N16869976: R215.2 U46.18(RXD3/AN1)
N16869978: R216.2 U46.13(RXCTL/PHY_AD2)
N16870294: R207.1 T1.15
N16870296: C302.1 R207.2 R208.2 R210.2 R212.2
N16870306: R208.1 T1.18
N16870310: R210.1 T1.21
N16870330: R212.1 T1.24
N16870380: C296.2 C298.2 C299.2 C301.2 T1.1 T1.4 T1.7 T1.10
N16870828: C297.1 FB26.2 J14.A11
N16870844: C307.1 J14.A12 R219.2
N16870890: C308.1 J14.A9 R218.2
N16871038: R221.1 U46.20(~{INT})
N16873302: C304.1 U46.42(CKXTAL1) Y1.1
N16873318: C305.1 U46.43(CKXTAL2) Y1.3
N16873350: R220.2 U46.29(~{PHYRST})
N16874872: C303.1 R217.1 U46.46(CLK125)
N16877780: R222.1 U46.33(~{PME})
N16879465: L3.1 R224.1 U46.48(REG_OUT)
N16880733: R822.2 U46.38(ENSWREG)
N16880820: C309.1 R224.2
N16890207: R227.2 U46.39(RSET)
N16891950: R265.1 T3.15
N16891952: C365.1 R265.2 R266.2 R267.2 R271.2
N16891962: R266.1 T3.18
N16891966: R267.1 T3.21
N16891978: R271.1 T3.24
N16892036: C360.2 C362.2 C363.2 C364.2 T3.1 T3.4 T3.7 T3.10
N16892171: C361.1 FB32.2 J42.9 J42.11
N16892215: C370.1 J42.10 R274.2
N16892219: C369.1 J42.12 R275.2
N16892768: R269.2 U52.43(RXD7/AN0)
N16892846: R270.2 U52.44(RXER/AN1)
N16894213: R272.2 U52.46(CRS/MII1)
N16894217: R273.2 U52.45(COL/MII0)
N16894418: R281.1 U52.75(~{INT})
N16899326: C366.1 U52.13(HSIP)
N16899338: C367.1 U52.14(HSIN)
N16900249: R276.1 U52.70(LED2/MDI0)
N16900569: R278.1 U52.71(LED3/MDI1)
N16900702: C372.1 U52.81(CKXTAL1) Y3.1
N16900720: C373.1 U52.82(CKXTAL2) Y3.3
N16900769: R280.2 U52.52(~{PHYRST})
N16902304: R827.2 U52.77(ENSWREG)
N16902556: R286.2 U52.26(REXT)
N16903120: R285.2 U52.78(RSET)
N16909680: L5.1 R284.1 U52.88(REG_OUT)
N16909742: C374.1 R284.2
N16927443: R268.2 U52.39(RXD4/SELRGV)
N16973728: L4.1 R253.1 U49.48(REG_OUT)
N16973810: R825.2 U49.38(ENSWREG)
N16973842: C341.1 R253.2
N16974061: C331.2 R238.2 U49.19(RXC)
N16974094: R239.2 U49.14(RXD0/SELRGV)
N16974110: R242.2 U49.16(RXD1/TXDLY)
N16974123: R243.2 U49.17(RXD2/AN0)
N16974136: R244.2 U49.18(RXD3/AN1)
N16974138: R245.2 U49.13(RXCTL/PHY_AD2)
N16974225: R236.1 T2.15
N16974227: C334.1 R236.2 R237.2 R240.2 R241.2
N16974244: R237.1 T2.18
N16974248: R240.1 T2.21
N16974260: R241.1 T2.24
N16974322: C328.2 C330.2 C332.2 C333.2 T2.1 T2.4 T2.7 T2.10
N16974528: C329.1 FB29.2 J14.B9
N16974538: C337.1 J14.B11 R248.2
N16974572: C338.1 J14.B10 R247.2
N16974631: R250.1 U49.20(~{INT})
N16974829: C339.1 U49.42(CKXTAL1) Y2.1
N16974847: C340.1 U49.43(CKXTAL2) Y2.3
N16974885: R249.2 U49.29(~{PHYRST})
N16975047: C335.1 R246.1 U49.46(CLK125)
N16975158: R251.1 U49.33(~{PME})
N16975193: R256.2 U49.39(RSET)
N17013042: L1.1 R167.1 U1.F1(USB1_UDP)
N17013078: L1.4 R168.1 U1.F2(USB1_UDM)
N17013302: R172.2 U1.H4(USB2_UID)
N17013307: R173.2 U1.F4(USB1_UID)
N17013374: C1022.1 R171.2 U1.G4(USB_IBIAS_REXT)
N17020476: L2.1 R169.1 U1.H1(USB2_UDP)
N17020482: L2.4 R170.1 U1.H2(USB2_UDM)
N17021052: FB9.1 J41.4
N17021059: FB7.1 J41.8
N17021121: Q3.3(D) R156.1 R157.1 U1.F5(USB1_PWRFAULT)
N17021131: Q4.3(D) R155.1 R160.1 U1.H5(USB2_PWRFAULT)
N17033690: C132.1 R175.1 X1.3(OUT)
N17033815: R174.2 X1.1(OE)
N17055310: C273.1 U39.2(V+)
N17055339: C275.1 U39.6(V-)
N17055373: C271.2 U39.1(C1+)
N17055376: C271.1 U39.3(C1-)
N17055394: C274.2 U39.4(C2+)
N17055396: C274.1 U39.5(C2-)
N17055419: R196.1 U39.14(T1-OUT)
N17055422: R197.1 U39.13(R1-IN)
N17055459: R199.1 U39.8(R2-IN)
N17055461: R198.1 U39.7(T2-OUT)
N17055495: FB18.1 R196.2
N17055507: FB19.1 R197.2
N17055527: FB20.1 R198.2
N17055529: FB21.1 R199.2
N17056698: C287.1 U41.2(V+)
N17056714: C288.1 U41.6(V-)
N17056740: C285.2 U41.1(C1+)
N17056750: C285.1 U41.3(C1-)
N17056764: C284.2 U41.4(C2+)
N17056766: C284.1 U41.5(C2-)
N17056776: R200.1 U41.14(T1-OUT)
N17056778: R201.1 U41.13(R1-IN)
N17056796: R203.1 U41.8(R2-IN)
N17056798: R202.1 U41.7(T2-OUT)
N17056816: FB22.1 R200.2
N17056834: FB23.1 R201.2
N17056844: FB24.1 R202.2
N17056846: FB25.1 R203.2
N18586245: C294.2 R205.2 U45.2(D+)
N18586247: C294.1 R206.2 U45.3(D-)
N19293526: D5.1 R186.2
N19295120: D6.1 R187.2
N20562350: C1022.2 R814.2
N21754633: J43.28 R867.1
N21754692: J43.36 R868.1
N21754708: J43.38 R869.1
N21824193: Q41.1(G) R860.2
N21824406: Q41.3(D) R859.2 U101.2(I1)

Not connected (* = marked no-connect by the designer): J13 A2* A7* B2* B7*; J43 8*; U1 AA6(NC08)* AA7(NC09)* AA8(NC10)* AA9(NC11)* AA10(NC12)* AB8(NC13)* AB11(NC14)* AB12(NC15)* AG28(NC_DET)* F10(TH_TPA)* G6(SPARE1)* G17(NC01)* H6(SPARE2)* J6(SPARE3)* N6(NC02)* T6(NC03)* U6(NC04)* V6(NC05)* W6(NC06)* Y6(NC07)*; U38 3*; U40 5(NC1)* 14(NC2)* 15(NC3)*; U42 5(NC1)* 14(NC2)* 15(NC3)*; U46 12(NC)*; U47 5*; U48 5*; U49 12(NC)*; U50 5*; U51 5*; U52 21(HSON_CK)* 22(HSOP_CK)* 28(NC1)* 29(NC2)* 30(NC3)* 31(NC4)* 32(RXDV/RXCTL)* 33(RXD0)* 35(RXD1)* 36(RXD2)* 37(RXD3)* 38(RXC)* 41(RXD5/TXDLY)* 42(RXD6/RXDLY)* 56(TXCLK)* 62(TMS)* 63(TCK)* 64(TDO)* 65(TDI)* 74(~{PME})* 76(NC5)* 86(CLK125)*; U53 5*; U54 5*; U96 3*

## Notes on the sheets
sheet 10
- T1040 QE INTERFACE
- TDM RISER CARD CONNECTOR
- T1040 ONLY!
- T1040 DVDD: 3.3V
sheet 11
- T1040 USB INTERFACE
- USB1&2 FOR HOST MODE
- FOR T1040/T2081, USBCLK OPERATES AT 1.8V
- USBCLK BELONGS TO O1VDD
- FOR INTERPOSER, USBCLK OPERATES AT 3.3V
sheet 12
- T1040 POWER SUPPLY
- USB_SVDD supply must ramp before or after the
  USB_HVDD and USB_OVDD supplies have ramped.
- USB_OVDD ONLY ON T1040/T2081
- LABEL = PROG_SFP
- THESE PINs ONLY ON T1040/T2081
- LABEL = PROG_MTR
- LABEL = FA_VDD
- THVDD ONLY ON T1040/T2081
sheet 13
- T1040 PLL FILTERs and GROUND
- LABEL = T1040/T1020
- LABEL = T2081
- THESE PINs ONLY ON T1040/T2081
sheet 14
- T1040 DUART and I2C DEVICE INTERFACE
- For RS232 ESD protection, place close to RJ45 connector
- I2C EEPROM
- I2C ADDR = 0x50
- I2C THERMAL MONITOR
- I2C ADDR = 0x4C
sheet 15
- RGMII ETHERNET PORT 1
- 100 ohms
  DIFF PAIRs
- For Gigabit Ethernet protection, place close to magnetics
- RGMII PHY POWER-ON STRAPPINGs
- SELRGV
- TXDLY
- 2.5V
- AN0
- NWay, advertize all capability
- AN1
- PHY_AD2
- PHY_AD0
- PHY ADDR = 0x01
- PHY_AD1
- RXDLY
sheet 16
- RGMII ETHERNET PORT 2
- 100 ohms
  DIFF PAIRs
- For Gigabit Ethernet protection, place close to magnetics
- RGMII PHY POWER-ON STRAPPINGs
- SELRGV
- TXDLY
- 2.5V
- AN0
- NWay, advertize all capability
- AN1
- PHY_AD2
- PHY_AD0
- PHY ADDR = 0x02
- PHY_AD1
- RXDLY
sheet 17
- SGMII ETHERNET PORT
- 100 ohms DIFF PAIR
- 100 ohms
  DIFF PAIRs
- 2.5V GMII/RGMII
- NWay, advertize all capability
- SGMII to Coper
- 100 ohms DIFF PAIR
- PHY ADDR = 0x03
- SGMII to Coper
- For Gigabit Ethernet protection, place close to magnetics
